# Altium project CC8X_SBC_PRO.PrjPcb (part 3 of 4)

## Sheet 11 - USB HUB.SchDoc: USB HUB
size A3; PageSetup: Record=PageOptions¦CenterHorizontal=True¦CenterVertical=True¦PrintScale=0.70¦XCorrection=1.00¦YCorrection=1.00¦PrintKind=0¦BorderSize=5000000¦LeftOffset=0¦BottomOffset=0¦Orientation=2¦PaperLength=4200¦PaperWidth=2970¦Scale=100¦PaperSource=7¦PrintQuality=600¦MediaType=1¦DitherType=10¦PaperKind=A4¦PrintScaleMode=1; Author: Juan Anzola; SheetNumber: 11; SheetTotal: 17
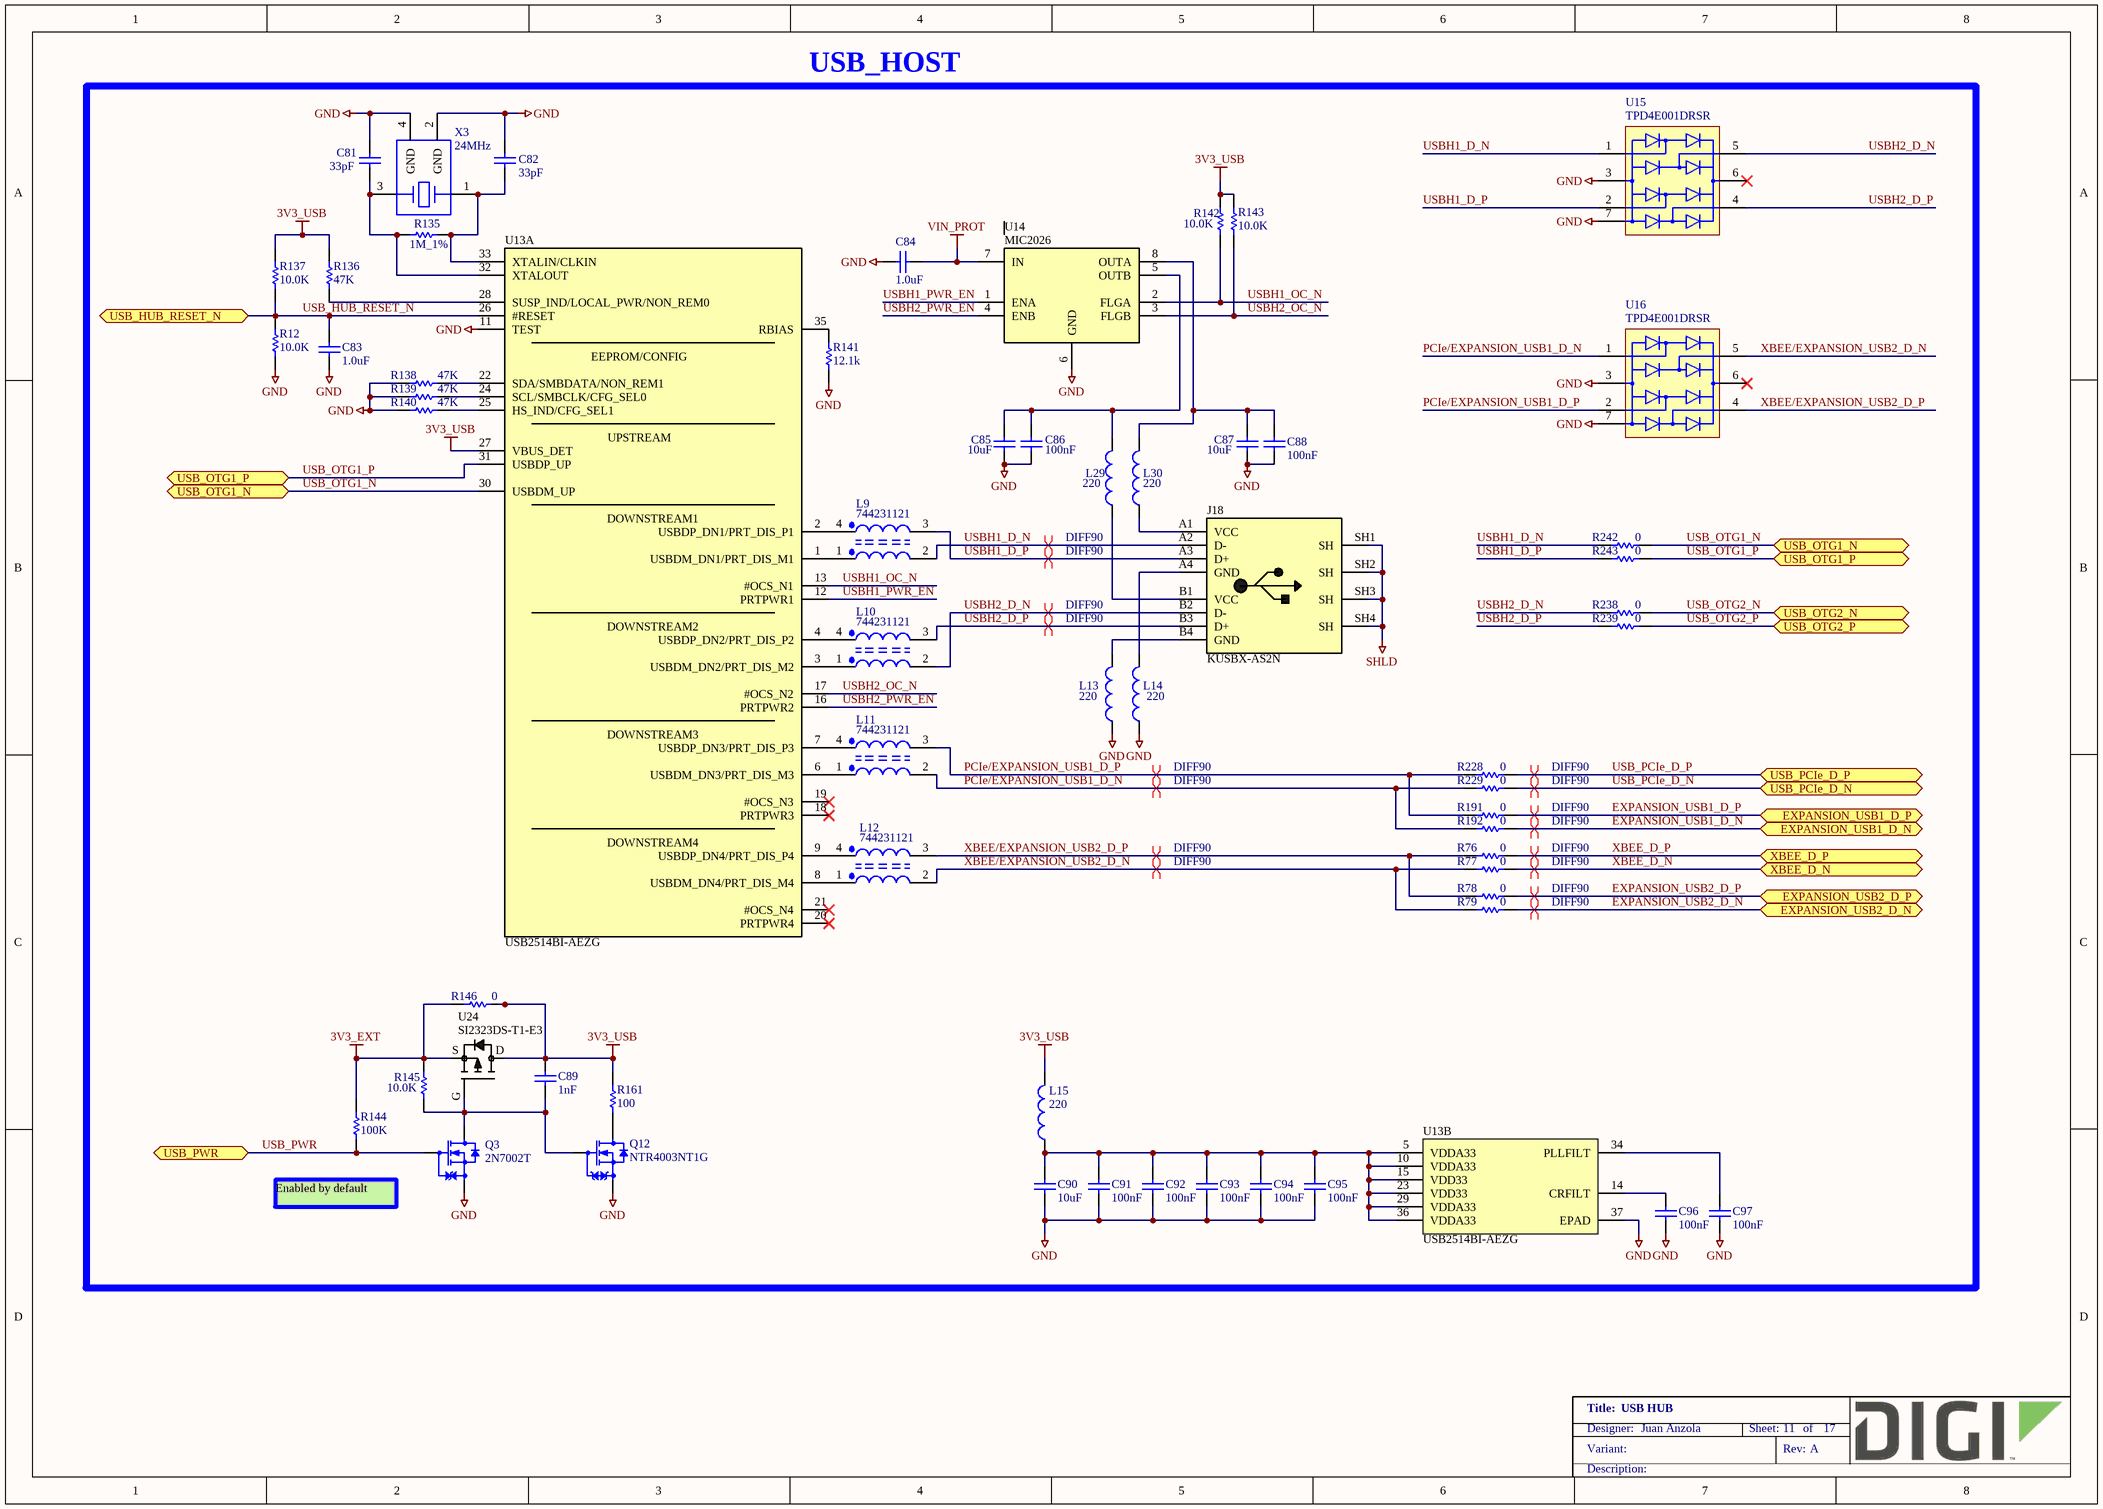
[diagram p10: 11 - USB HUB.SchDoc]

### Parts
C81  33pF  [CAPC1005X55N]
C82  33pF  [CAPC1005X55N]
C83  1.0uF  [CAPC1005X55N]
C84  1.0uF  [CAPC1005X55N]
C85  10uF  [CAPC1005X55N]
C86  100nF  [CAPC1005X55N]
C87  10uF  [CAPC1005X55N]
C88  100nF  [CAPC1005X55N]
C89  1nF  [CAPC1005X55N]
C90  10uF  [CAPC1005X55N]
C91  100nF  [CAPC1005X55N]
C92  100nF  [CAPC1005X55N]
C93  100nF  [CAPC1005X55N]
C94  100nF  [CAPC1005X55N]
C95  100nF  [CAPC1005X55N]
C96  100nF  [CAPC1005X55N]
C97  100nF  [CAPC1005X55N]
J18  KUSBX-AS2N  [KYCON_KUSBX-AS2N_Flex]
L9  744231121  [FIL_DLW21H]
L10  744231121  [FIL_DLW21H]
L11  744231121  [FIL_DLW21H]
L12  744231121  [FIL_DLW21H]
L13  220  [INDC2013X110N]
L14  220  [INDC2013X110N]
L15  220  [INDC2013X110N]
L29  220  [INDC2013X110N]
L30  220  [INDC2013X110N]
Q3  2N7002T  [SOTFL50P160X80_GSD-3N]
Q12  NTR4003NT1G  [SOT95P240X110_GSD-3N]
R12  10.0K  [RESC1005X40N]
R76  0  [RESC1005X40N]
R77  0  [RESC1005X40N]
R78  0  [RESC1005X40N]
R79  0  [RESC1005X40N]
R135  1M_1%  [RESC1005X40N]
R136  47K  [RESC1005X40N]
R137  10.0K  [RESC1005X40N]
R138  47K  [RESC1005X40N]
R139  47K  [RESC1005X40N]
R140  47K  [RESC1005X40N]
R141  12.1k  [RESC1005X40N]
R142  10.0K  [RESC1005X40N]
R143  10.0K  [RESC1005X40N]
R144  100K  [RESC1005X40N]
R145  10.0K  [RESC1005X40N]
R146  0  [RESC1609X55N]
R161  100  [RESC1005X40N]
R191  0  [RESC1005X40N]
R192  0  [RESC1005X40N]
R228  0  [RESC1005X40N]
R229  0  [RESC1005X40N]
R238  0  [RESC1005X40N]
R239  0  [RESC1005X40N]
R242  0  [RESC1005X40N]
R243  0  [RESC1005X40N]
U13  USB2514BI-AEZG  [QFN50P600X600X100-37AN]  (parts A,B of 2)
U14  MIC2026  [SOIC127P600X175-8N]
U15  TPD4E001DRSR  [SON95P300X300X80-7N]
U16  TPD4E001DRSR  [SON95P300X300X80-7N]
U24  SI2323DS-T1-E3  [SOT95P240X110_GSD-3N]
X3  24MHz  [XTAL_C3E-3427]

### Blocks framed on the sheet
USB_HOST: C81-C97 J18 L9-L15 L29 L30 Q3 Q12 R12 R76-R79 R135-R146 R161 R191 R192 R228 R229 R238 R239 R242 R243 U13-U16 U24 X3

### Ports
EXPANSION_USB1_D_N (bidir), EXPANSION_USB1_D_P (bidir), EXPANSION_USB2_D_N (bidir), EXPANSION_USB2_D_P (bidir), USB_HUB_RESET_N (bidir), USB_OTG1_N (bidir), USB_OTG1_P (bidir), USB_OTG2_N (bidir), USB_OTG2_P (bidir), USB_PCIe_D_N (bidir), USB_PCIe_D_P (bidir), USB_PWR (bidir), XBEE_D_N (bidir), XBEE_D_P (bidir)

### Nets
3V3_EXT: R144.1 R145.1 R146.1 U24.S
3V3_USB: C89.2 L15.2 R136.2 R137.2 R142.2 R143.2 R146.2 R161.2 U13.27(VBUS_DET) U24.D
GND: C81.2 C82.2 C83.1 C84.2 C85.1 C86.1 C87.1 C88.1 C90.1 C91.1 C92.1 C93.1 C94.1 C95.1 C96.1 C97.1 L13.1 L14.1 Q3.S Q12.S R12.1 R138.1 R139.1 R140.1 R141.1 U13.11(TEST) U13.37(EPAD) U14.6(GND) U15.3(GND) U15.7(GND) U16.3(GND) U16.7(GND) X3.2(GND) X3.4(GND)
SHLD: J18.SH1(SH) J18.SH2(SH) J18.SH3(SH) J18.SH4(SH)
VIN_PROT: C84.1 U14.7(IN)
EXPANSION_USB1_D_N: R192.2 ; port EXPANSION_USB1_D_N
EXPANSION_USB1_D_P: R191.2 ; port EXPANSION_USB1_D_P
EXPANSION_USB2_D_N: R79.2 ; port EXPANSION_USB2_D_N
EXPANSION_USB2_D_P: R78.2 ; port EXPANSION_USB2_D_P
PCIe/EXPANSION_USB1_D_N: L11.2 R192.1 R229.1 U16.1(I/O)
PCIe/EXPANSION_USB1_D_P: L11.3 R191.1 R228.1 U16.2(I/O)
USB_HUB_RESET_N: C83.2 R12.2 R137.1 U13.26(#RESET) ; port USB_HUB_RESET_N
USB_OTG1_N: R242.2 U13.30(USBDM_UP) ; port USB_OTG1_N
USB_OTG1_P: R243.2 U13.31(USBDP_UP) ; port USB_OTG1_P
USB_OTG2_N: R238.2 ; port USB_OTG2_N
USB_OTG2_P: R239.2 ; port USB_OTG2_P
USB_PCIe_D_N: R229.2 ; port USB_PCIe_D_N
USB_PCIe_D_P: R228.2 ; port USB_PCIe_D_P
USB_PWR: Q3.G R144.2 ; port USB_PWR
USBH1_D_N: J18.A2(D-) L9.2 R242.1 U15.1(I/O)
USBH1_D_P: J18.A3(D+) L9.3 R243.1 U15.2(I/O)
USBH1_OC_N: R142.1 U13.13(#OCS_N1) U14.2(FLGA)
USBH1_PWR_EN: U13.12(PRTPWR1) U14.1(ENA)
USBH2_D_N: J18.B2(D-) L10.2 R238.1 U15.5(I/O)
USBH2_D_P: J18.B3(D+) L10.3 R239.1 U15.4(I/O)
USBH2_OC_N: R143.1 U13.17(#OCS_N2) U14.3(FLGB)
USBH2_PWR_EN: U13.16(PRTPWR2) U14.4(ENB)
XBEE/EXPANSION_USB2_D_N: L12.2 R77.1 R79.1 U16.5(I/O)
XBEE/EXPANSION_USB2_D_P: L12.3 R76.1 R78.1 U16.4(I/O)
XBEE_D_N: R77.2 ; port XBEE_D_N
XBEE_D_P: R76.2 ; port XBEE_D_P
NetC81_1: C81.1 R135.1 U13.32(XTALOUT) X3.3
NetC82_1: C82.1 R135.2 U13.33(XTALIN/CLKIN) X3.1
NetC85_2: C85.2 C86.2 L29.2 U14.5(OUTB)
NetC87_2: C87.2 C88.2 L30.2 U14.8(OUTA)
NetC89_1: C89.1 Q3.D Q12.G R145.2 U24.G
NetC90_2: C90.2 C91.2 C92.2 C93.2 C94.2 C95.2 L15.1 U13.5(VDDA33) U13.10(VDDA33) U13.15(VDD33) U13.23(VDD33) U13.29(VDDA33) U13.36(VDDA33)
NetC96_2: C96.2 U13.14(CRFILT)
NetC97_2: C97.2 U13.34(PLLFILT)
NetJ18_A1: J18.A1(VCC) L30.1
NetJ18_A4: J18.A4(GND) L14.2
NetJ18_B1: J18.B1(VCC) L29.1
NetJ18_B4: J18.B4(GND) L13.2
NetL9_1: L9.1 U13.1(USBDM_DN1/PRT_DIS_M1)
NetL9_4: L9.4 U13.2(USBDP_DN1/PRT_DIS_P1)
NetL10_1: L10.1 U13.3(USBDM_DN2/PRT_DIS_M2)
NetL10_4: L10.4 U13.4(USBDP_DN2/PRT_DIS_P2)
NetL11_1: L11.1 U13.6(USBDM_DN3/PRT_DIS_M3)
NetL11_4: L11.4 U13.7(USBDP_DN3/PRT_DIS_P3)
NetL12_1: L12.1 U13.8(USBDM_DN4/PRT_DIS_M4)
NetL12_4: L12.4 U13.9(USBDP_DN4/PRT_DIS_P4)
NetQ12_D: Q12.D R161.1
NetR136_1: R136.1 U13.28(SUSP_IND/LOCAL_PWR/NON_REM0)
NetR138_2: R138.2 U13.22(SDA/SMBDATA/NON_REM1)
NetR139_2: R139.2 U13.24(SCL/SMBCLK/CFG_SEL0)
NetR140_2: R140.2 U13.25(HS_IND/CFG_SEL1)
NetR141_2: R141.2 U13.35(RBIAS)

Not connected (* = marked no-connect by the designer): U13 18(PRTPWR3)* 19(#OCS_N3)* 20(PRTPWR4)* 21(#OCS_N4)*; U15 6(VCC)*; U16 6(VCC)*

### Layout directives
differential pair; net class DIFF90: EXPANSION_USB1_D_N, EXPANSION_USB1_D_P, EXPANSION_USB2_D_N, EXPANSION_USB2_D_P, PCIe/EXPANSION_USB1_D_N, PCIe/EXPANSION_USB1_D_P, USB_PCIe_D_N, USB_PCIe_D_P, USBH1_D_N, USBH1_D_P, USBH2_D_N, USBH2_D_P, XBEE/EXPANSION_USB2_D_N, XBEE/EXPANSION_USB2_D_P, XBEE_D_N, XBEE_D_P

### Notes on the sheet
- Enabled by default

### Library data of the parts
C81 C82 = 1002646: CAP CER 33PF 50V C0G/NP0 0402; Part_Type: Capacitor; Manufacturer: Murata; Manufacturer_Part_Number: GCM1555C1H330JA16D; Digi_PN: 14050400; Component_Life_Cycle_State: Reviewed; Area: 2,12; Voltage: 50; Tolerance: 5%
C83 C84 = 1001167: CAP CER 1UF 10V 10% X5R 0402; Part_Type: Capacitor; Manufacturer: Murata; Manufacturer_Part_Number: GRM155R61A105KE15D; Digi_PN: 14050399; Component_Life_Cycle_State: Reviewed; Area: 0.95; Project: CCWMX6_SBC board
C85 C87 C90 = 1001168: CAP CER 10UF 10V 20% X5R 0402; Part_Type: Capacitor; Manufacturer: Samsung; Manufacturer_Part_Number: CL05A106MP5NUNC; Digi_PN: 14050689; Component_Life_Cycle_State: Reviewed; Area: 0.95; Project: CCWMX6_SBC board
C86 C88 C91-C97 = 1000006: CAP 100nF 16V 10% X7R 0402; Part_Type: Capacitor; Manufacturer: Murata; Manufacturer_Part_Number: GRM155R71C104KA88D; Component_Life_Cycle_State: CAD Reviewed; Area: 0.95; Project: KITT; Tolerance: 10; Digi_PN: 14050552
C89 = 1000067: CAP CER 1000PF 50V 10% X7R 0402; Part_Type: Capacitor; Manufacturer: Murata; Manufacturer_Part_Number: GRM155R71H102KA01D; Digi_PN: 14050737; Component_Life_Cycle_State: Proven; Area: 0,95; Project: Adjustable Foundation
J18 = 1001121: USB Stacked Dual A type; Part_Type: Connector; Manufacturer: KYCON; Digi_PN: 18000276; Component_Life_Cycle_State: Reviewed; Area: 164; Project: CCWMX6_SBC board
L9-L12 = 1001173: CHOKE COM MODE 120 OHM .37A; Part_Type: Inductor; Manufacturer: Wurth Electronics Inc; Digi_PN: 21000143; Component_Life_Cycle_State: Reviewed; Area: 2.4; Project: CCWMX6_SBC board
L13-L15 L29 L30 = 1001174: FERRITE BEAD 220 OHM 2.0A 0805; Manufacturer: Wurth Electronics Inc; Manufacturer_Part_Number: 742792022; Digi_PN: 21000146; Component_Life_Cycle_State: Reviewed; Area: 4.24; Project: CCWMX6_SBC board
Q3 = 1000715: MOSFET N-CH 60V 115MA SOT-523F; Part_Type: Transistor; Manufacturer: Fairchild Semiconductor; Digi_PN: 17050797; Component_Life_Cycle_State: CAD Reviewed; Area: 3.06; Project: SmartMeter2; Note: 17050841 = Digi No. for GE WDNU
Q12 = 1000306: MOSFET N-CH 30V 500MA SOT-23; Part_Type: Transistor; Manufacturer: On Semiconductor; Digi_PN: 17050809; Component_Life_Cycle_State: Proven; Area: 10,92; Project: Adjustable Foundation
R12 R137 R142 R143 R145 = 1000537: RES 10.0K OHM 1/10W 1% 0402 SMD; Part_Type: Resistor; Manufacturer: Panasonic - ECG; Manufacturer_Part_Number: ERJ-2RKF1002X; Component_Life_Cycle_State: CAD Reviewed; Area: 0.95; Project: KITT; Power_WV_SRF: 100; Digi_PN: 13051084
R76-R79 R191 R192 R228 R229 R238 R239 R242 R243 = 1000076: RES 0.0 OHM 1/10W 0402 SMD; Part_Type: Resistor; Manufacturer: Panasonic - ECG; Manufacturer_Part_Number: ERJ-2GE0R00X; Component_Life_Cycle_State: Proven; Area: 0.95; Project: Adjustable Foundation; Power_WV_SRF: 10; Digi_PN: 13050387
R135 = 1000971: RES 1.00M OHM 1/16W 1% 0402 SMD; Part_Type: Resistor; Manufacturer: Yageo; Manufacturer_Part_Number: RC0402FR-071ML; Digi_PN: 13050561; Component_Life_Cycle_State: Reviewed; Area: 0.95; Project: ConnectCore i.MX6 module; Power_WV_SRF: 63; Tolerance: 1; Note: 13051098 = Digi No. for GE WDNU
R136 R138-R140 = 1001155: RES 47.0K OHM 1/16W 1% 0402 SMD; Part_Type: Resistor; Manufacturer: Vishay Dale; Manufacturer_Part_Number: CRCW040247K0FKED; Digi_PN: 13050646; Component_Life_Cycle_State: Reviewed; Area: 0.95; Project: CCWMX6_SBC board
R141 = 1000828: RES 12.1K OHM 1/10W 1% 0402 SMD; Part_Type: Resistor; Manufacturer: Panasonic - ECG; Manufacturer_Part_Number: ERJ-2RKF1212X; Component_Life_Cycle_State: Reviewed; Area: 0.95; Project: SmartMeter2; Power_WV_SRF: 100; Digi_PN: 13051088
R144 = 1000480: RES 100K OHM 1/10W 1% 0402 SMD; Part_Type: Resistor; Manufacturer: Panasonic - ECG; Manufacturer_Part_Number: ERJ-2RKF1003X; Digi_PN: 13051063; Component_Life_Cycle_State: CAD Reviewed; Area: 0.95; Project: KITT; Power_WV_SRF: 100
R146 = 1000208: RES 0.0 OHM 1/10W 0603; Part_Type: Resistor; Manufacturer: Panasonic - ECG; Manufacturer_Part_Number: ERJ-3GEY0R00V; Note: 13051103 = Digi No. for GE WDNU; Digi_PN: 13050568; Component_Life_Cycle_State: Reviewed; Area: 2.5; Project: Adjustable Foundation; Voltage: 75V
R161 = 1000467: RES 100 OHM 1/10W 1% 0402 SMD; Part_Type: Resistor; Manufacturer: Panasonic - ECG; Manufacturer_Part_Number: ERJ-2RKF1000X; Digi_PN: 13051087; Component_Life_Cycle_State: CAD Reviewed; Area: 0,95; Project: KITT
U13 = 1001114: 4-PORT USB 2.0 HUB CTRLR 36VQFN; Part_Type: IC; Manufacturer: SMSC; Digi_PN: 16051280; Component_Life_Cycle_State: Reviewed; Area: 36; Project: CCWMX6_SBC board
U14 = 1001143: IC SW DISTRIBUTION 2CHAN 8SOIC; Manufacturer: Micrel; Manufacturer_Part_Number: MIC2026-1YM; Digi_PN: 16051879; Component_Life_Cycle_State: Reviewed; Area: 29.58; Project: CCWMX6_SBC board
U15 U16 = 1001265: TVS DIODE 5.5VWM 6SON; Part_Type: IC; Manufacturer: Texas Instruments; Digi_PN: 17050690; Component_Life_Cycle_State: Reviewed; Area: 10; Project: CCWMX6_SBC board; Note: 17050839 = Digi No. for GE WDNU
U24 = 1001163: MOSFET P-CH 20V 3.7A SOT23-3; Part_Type: IC; Manufacturer: Vishay Siliconix; Digi_PN: 17050358; Component_Life_Cycle_State: Reviewed; Area: 10.92; Project: CCWMX6_SBC board
X3 = 1001134: CRYSTAL 24MHZ 18PF SMD; Part_Type: Crystals-Oscillators; Manufacturer: Aker; Manufacturer_Part_Number: C3E-24.000-18-3030-X-R; Digi_PN: 20000223; Component_Life_Cycle_State: Reviewed; Area: 9.18; Project: CCWMX6_SBC board

## Sheet 12 - USB Type C, USB microAB.SchDoc: USB Type C, USB mciroAB
size A3; PageSetup: Record=PageOptions¦CenterHorizontal=True¦CenterVertical=True¦PrintScale=0.70¦XCorrection=1.00¦YCorrection=1.00¦PrintKind=0¦BorderSize=5000000¦LeftOffset=0¦BottomOffset=0¦Orientation=2¦PaperLength=4200¦PaperWidth=2970¦Scale=100¦PaperSource=7¦PrintQuality=600¦MediaType=1¦DitherType=10¦PaperKind=A4¦PrintScaleMode=1; Author: Juan Anzola; SheetNumber: 12; SheetTotal: 17
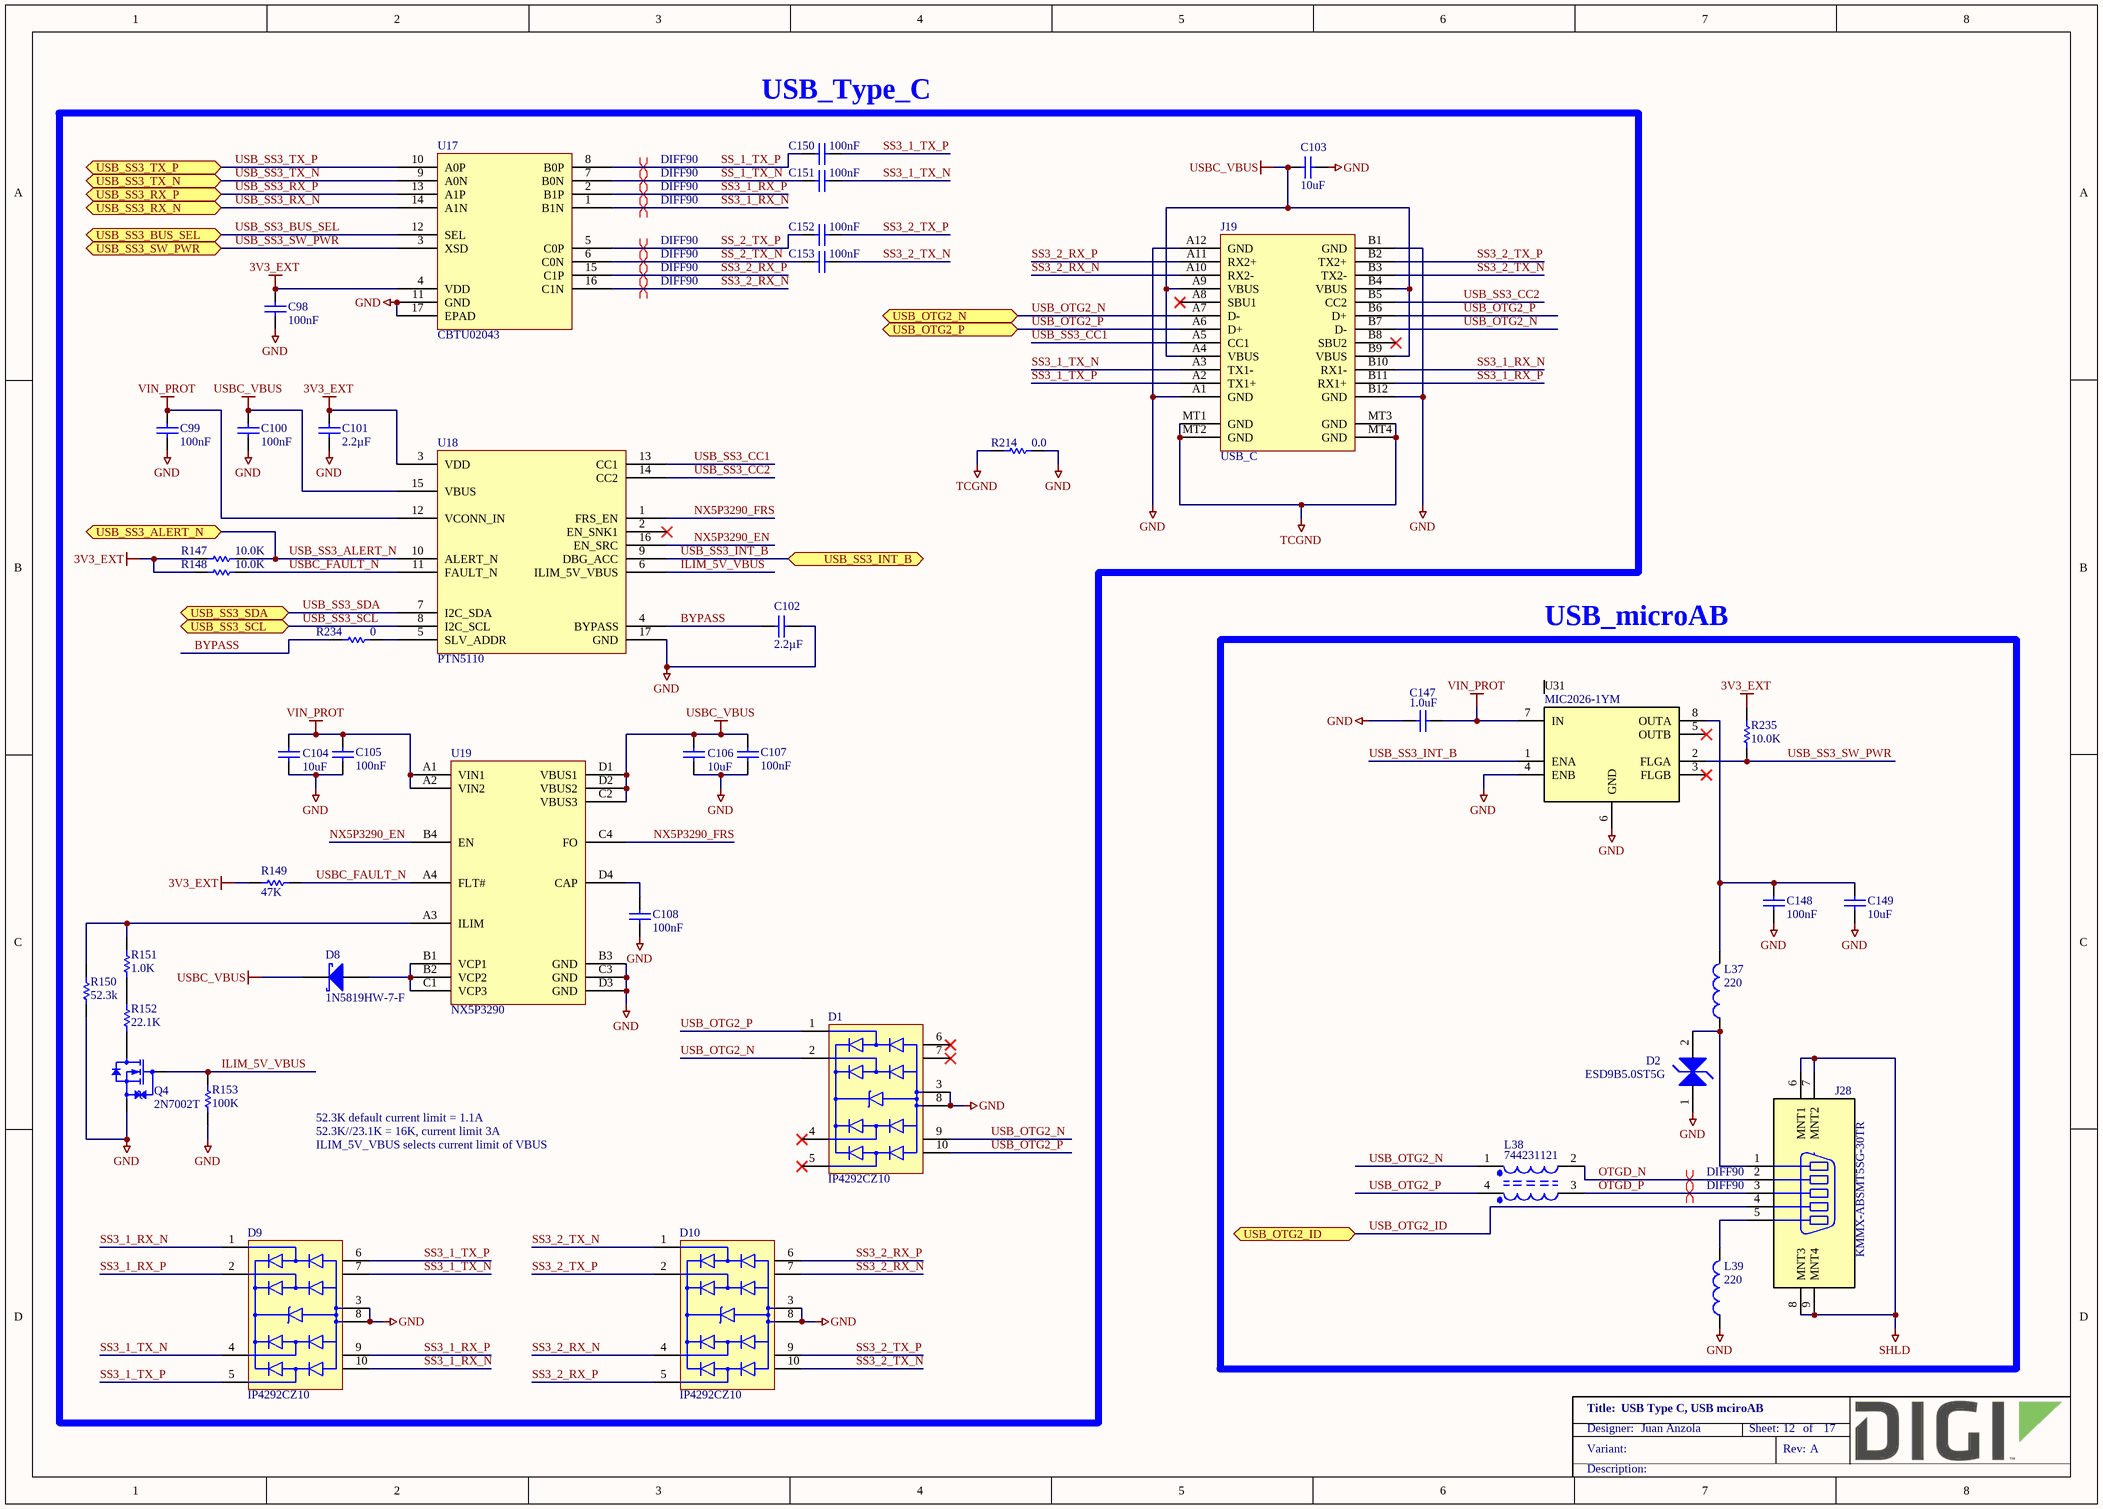
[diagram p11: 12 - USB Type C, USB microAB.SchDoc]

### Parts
C98  100nF  [CAPC1005X55N]
C99  100nF  [CAPC1005X55N]
C100  100nF  [CAPC1005X55N]
C101  2.2µF  [CAPC1005X55L]
C102  2.2µF  [CAPC1005X55L]
C103  10uF  [CAPC1005X55N]
C104  10uF  [CAPC1005X55N]
C105  100nF  [CAPC1005X55N]
C106  10uF  [CAPC1005X55N]
C107  100nF  [CAPC1005X55N]
C108  100nF  [CAPC1005X55N]
C147  1.0uF  [CAPC1005X55N]
C148  100nF  [CAPC1005X55N]
C149  10uF  [CAPC1005X55N]
C150  100nF  [CAPC1005X55N]
C151  100nF  [CAPC1005X55N]
C152  100nF  [CAPC1005X55N]
C153  100nF  [CAPC1005X55N]
D1  IP4292CZ10  [SON50P250X100X50-10N]
D2  ESD9B5.0ST5G  [SODFL1006X43N12]
D8  1N5819HW-7-F  [SOD3716X135N]
D9  IP4292CZ10  [SON50P250X100X50-10N]
D10  IP4292CZ10  [SON50P250X100X50-10N]
J19  USB_C  [MOLEX_201267-0005]
J28  KMMX-ABSMT5SG-30TR  [KYCON_KMMX-ABSMT5]
L37  220  [INDC2013X110N]
L38  744231121  [FIL_DLW21H]
L39  220  [INDC2013X110N]
Q4  2N7002T  [SOTFL50P160X80_GSD-3N]
R147  10.0K  [RESC1005X40N]
R148  10.0K  [RESC1005X40N]
R149  47K  [RESC1005X40N]
R150  52.3k  [RESC1005X40N]
R151  1.0K  [RESC1005X40N]
R152  22.1K  [RESC1005X40N]
R153  100K  [RESC1005X40N]
R214  0.0  [RESC2013X70N]
R234  0  [RESC1005X40N]
R235  10.0K  [RESC1005X40N]
U17  CBTU02043  [PQFN40P160X240X55-17T140X60N]
U18  PTN5110  [QFN40P260X260X40-17T100X110N]
U19  NX5P3290  [BGA16N50P4X4_205X205X59B32N]
U31  Manufacturer_Part_Number: MIC2026-1YM  [SOIC127P600X175-8N]  (hidden comment: MIC2026)

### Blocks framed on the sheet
USB_Type_C: C98-C108 C150-C153 D1 D8-D10 J19 Q4 R147-R153 R214 R234 U17-U19
USB_microAB: C147-C149 D2 J28 L37-L39 R235 U31

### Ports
USB_OTG2_ID (bidir), USB_OTG2_N (bidir), USB_OTG2_P (bidir), USB_SS3_ALERT_N (bidir), USB_SS3_BUS_SEL (bidir), USB_SS3_INT_B (bidir), USB_SS3_RX_N (bidir), USB_SS3_RX_P (bidir), USB_SS3_SCL (bidir), USB_SS3_SDA (bidir), USB_SS3_SW_PWR (bidir), USB_SS3_TX_N (bidir), USB_SS3_TX_P (bidir)

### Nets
3V3_EXT: C98.2 C101.2 R147.1 R148.1 R149.1 R235.2 U17.4(VDD) U18.3(VDD)
GND: C98.1 C99.1 C100.1 C101.1 C102.1 C103.1 C104.1 C105.1 C106.1 C107.1 C108.1 C147.1 C148.1 C149.1 D1.3(GND) D1.8(GND) D2.1 D9.3(GND) D9.8(GND) D10.3(GND) D10.8(GND) J19.A1(GND) J19.A12(GND) J19.B1(GND) J19.B12(GND) L39.1 Q4.S R150.1 R153.1 R214.2 U17.11(GND) U17.17(EPAD) U18.17(GND) U19.B3(GND) U19.C3(GND) U19.D3(GND) U31.4(ENB) U31.6(GND)
SHLD: J28.6(MNT1) J28.7(MNT2) J28.8(MNT3) J28.9(MNT4)
TCGND: J19.MT1(GND) J19.MT2(GND) J19.MT3(GND) J19.MT4(GND) R214.1
USBC_VBUS: C100.2 C103.2 C106.2 C107.2 D8.K J19.A4(VBUS) J19.A9(VBUS) J19.B4(VBUS) J19.B9(VBUS) U18.15(VBUS) U19.C2(VBUS3) U19.D1(VBUS1) U19.D2(VBUS2)
VIN_PROT: C99.2 C104.2 C105.2 C147.2 U18.12(VCONN_IN) U19.A1(VIN1) U19.A2(VIN2) U31.7(IN)
BYPASS: C102.2 R234.2 U18.4(BYPASS)
ILIM_5V_VBUS: Q4.G R153.2 U18.6(ILIM_5V_VBUS)
NX5P3290_EN: U18.16(EN_SRC) U19.B4(EN)
NX5P3290_FRS: U18.1(FRS_EN) U19.C4(FO)
OTGD_N: J28.2 L38.2
OTGD_P: J28.3 L38.3
SS3_1_RX_N: D9.1(CH1) D9.10(NC) J19.B10(RX1-) U17.1(B1N)
SS3_1_RX_P: D9.2(CH2) D9.9(NC) J19.B11(RX1+) U17.2(B1P)
SS3_1_TX_N: C151.2 D9.4(CH3) D9.7(NC) J19.A3(TX1-)
SS3_1_TX_P: C150.2 D9.5(CH4) D9.6(NC) J19.A2(TX1+)
SS3_2_RX_N: D10.4(CH3) D10.7(NC) J19.A10(RX2-) U17.16(C1N)
SS3_2_RX_P: D10.5(CH4) D10.6(NC) J19.A11(RX2+) U17.15(C1P)
SS3_2_TX_N: C153.2 D10.1(CH1) D10.10(NC) J19.B3(TX2-)
SS3_2_TX_P: C152.2 D10.2(CH2) D10.9(NC) J19.B2(TX2+)
SS_1_TX_N: C151.1 U17.7(B0N)
SS_1_TX_P: C150.1 U17.8(B0P)
SS_2_TX_N: C153.1 U17.6(C0N)
SS_2_TX_P: C152.1 U17.5(C0P)
USB_OTG2_ID: J28.4 ; port USB_OTG2_ID
USB_OTG2_N: D1.2(CH2) D1.9(NC) J19.A7(D-) J19.B7(D-) L38.1 ; port USB_OTG2_N
USB_OTG2_P: D1.1(CH1) D1.10(NC) J19.A6(D+) J19.B6(D+) L38.4 ; port USB_OTG2_P
USB_SS3_ALERT_N: R147.2 U18.10(ALERT_N) ; port USB_SS3_ALERT_N
USB_SS3_BUS_SEL: U17.12(SEL) ; port USB_SS3_BUS_SEL
USB_SS3_CC1: J19.A5(CC1) U18.13(CC1)
USB_SS3_CC2: J19.B5(CC2) U18.14(CC2)
USB_SS3_INT_B: U18.9(DBG_ACC) U31.1(ENA) ; port USB_SS3_INT_B
USB_SS3_RX_N: U17.14(A1N) ; port USB_SS3_RX_N
USB_SS3_RX_P: U17.13(A1P) ; port USB_SS3_RX_P
USB_SS3_SCL: U18.8(I2C_SCL) ; port USB_SS3_SCL
USB_SS3_SDA: U18.7(I2C_SDA) ; port USB_SS3_SDA
USB_SS3_SW_PWR: R235.1 U17.3(XSD) U31.2(FLGA) ; port USB_SS3_SW_PWR
USB_SS3_TX_N: U17.9(A0N) ; port USB_SS3_TX_N
USB_SS3_TX_P: U17.10(A0P) ; port USB_SS3_TX_P
USBC_FAULT_N: R148.2 R149.2 U18.11(FAULT_N) U19.A4(FLT#)
NetC108_2: C108.2 U19.D4(CAP)
NetC148_2: C148.2 C149.2 L37.2 U31.8(OUTA)
NetD2_2: D2.2 J28.1 L37.1
NetD8_A: D8.A U19.B1(VCP1) U19.B2(VCP2) U19.C1(VCP3)
NetJ28_5: J28.5 L39.2
NetQ4_D: Q4.D R152.1
NetR150_2: R150.2 R151.2 U19.A3(ILIM)
NetR151_1: R151.1 R152.2
NetR234_1: R234.1 U18.5(SLV_ADDR)

Not connected (* = marked no-connect by the designer): D1 4(CH3)* 5(CH4)* 6(NC)* 7(NC)*; J19 A8(SBU1)* B8(SBU2)*; U18 2(EN_SNK1)*; U31 3(FLGB)* 5(OUTB)*

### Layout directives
differential pair; net class DIFF90: OTGD_N, OTGD_P, SS3_1_RX_N, SS3_1_RX_P, SS3_2_RX_N, SS3_2_RX_P, SS_1_TX_N, SS_1_TX_P, SS_2_TX_N, SS_2_TX_P

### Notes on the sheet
- 52.3K default current limit = 1.1A
- 52.3K//23.1K = 16K, current limit 3A
- ILIM_5V_VBUS selects current limit of VBUS

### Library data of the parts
C98-C100 C105 C107 C108 C148 = 1000006: as C86 on sheet 11 - USB HUB
C101 C102 = 1000970: CAP CER 2.2UF 6.3V 20% X5R 0402; Part_Type: Capacitor; Manufacturer: TDK Corporation; Manufacturer_Part_Number: C1005X5R0J225M050BC; Manufacturer_Alt_1: Taiyo Yuden; Manufacturer_Alt_1_Part_Number: JMK105BJ225MV-F; Note: 14050756 = Digi No. for GE WDNU; Digi_PN: 14050493; Component_Life_Cycle_State: Reviewed; Area: 0.5; Project: ConnectCore i.MX6 module; Tolerance: 20
C103 C104 C106 C149 = 1001168: as C85 on sheet 11 - USB HUB
C147 = 1001167: as C83 on sheet 11 - USB HUB
C150-C153 = 1000918: CAP CER 0.1UF 50V 10% X7R 0402; Part_Type: Capacitor; Manufacturer: TDK Corporation; Manufacturer_Part_Number: C1005X7R1H104K050BB; Digi_PN: 14050715; Component_Life_Cycle_State: Reviewed; Area: 0,95; Project: DTM3.0
D1 D9 D10 = 1002593: TVS DIODE 5.5V 4V 10DFN; Part_Type: Circuit Protection; Manufacturer: Phillips NXP; Digi_PN: 17000143; Component_Life_Cycle_State: Created; Area: 7,24; Project: DIGI CC8X SOM
D2 = 1001264: TVS DIODE 5VWM SOD923; Part_Type: Diodes; Manufacturer: On Semiconductor; Digi_PN: 17050587; Component_Life_Cycle_State: Reviewed; Area: 1.5; Project: CCWMX6_SBC board
D8 = 1000231: DIODE SCHOTTKY 40V 1A SOD123; Part_Type: Diodes; Manufacturer: Diodes, Inc.; Digi_PN: 17000146; Component_Life_Cycle_State: Proven; Area: 8.28; Project: Adjustable Foundation
J19 = 1002675: USB 3.1 SHIELDED I/O RECP TYPE C GEN2; Part_Type: Connector; Manufacturer: Molex; Manufacturer_Part_Number: 201267-0005; Digi_PN: 18000775; Component_Life_Cycle_State: Created; Area: 86.57; Project: DIGI CC8X SOM
J28 = 1001117: CONN RECEPT MICRO-USB TYPE AB R/A; Part_Type: Connector; Manufacturer: KYCON; Digi_PN: 18000401; Component_Life_Cycle_State: Reviewed; Area: 40; Project: CCWMX6_SBC board
L37 L39 = 1001174: as L13-L15 on sheet 11 - USB HUB
L38 = 1001173: as L9 on sheet 11 - USB HUB
Q4 = 1000715: as Q3 on sheet 11 - USB HUB
R147 R148 R235 = 1000537: as R12 on sheet 11 - USB HUB
R149 = 1001155: RES 47.0K OHM 1/16W 1% 0402 SMD; Part_Type: Resistor; Manufacturer: Vishay Dale; Manufacturer_Part_Number: CRCW040247K0FKED; Digi_PN: 13050646; Component_Life_Cycle_State: Reviewed; Area: 0,95; Project: CCWMX6_SBC board
R150 = 1000170: RES 52.3K OHM 1/10W 1% 0402 SMD; Part_Type: Resistor; Manufacturer: Panasonic - ECG; Manufacturer_Part_Number: ERJ-2RKF5232X; Digi_PN: 13000085; Component_Life_Cycle_State: Reviewed; Area: 0.95; Project: USB UART to USB Transceiver; Power_WV_SRF: 10
R151 = 1000079: RES 1.00K OHM 1/10W 1% 0402 SMD; Part_Type: Resistor; Manufacturer: Panasonic - ECG; Manufacturer_Part_Number: ERJ-2RKF1001X; Digi_PN: 13051085; Component_Life_Cycle_State: Proven; Area: 0,95; Project: Adjustable Foundation; Power_WV_SRF: 10
R152 = 1001149: RES 22.1K OHM 1/16W 1% 0402 SMD; Part_Type: Resistor; Manufacturer: Vishay Dale; Manufacturer_Part_Number: CRCW040222K1FKED; Digi_PN: 13050450; Component_Life_Cycle_State: Reviewed; Area: 0,95; Project: CCWMX6_SBC board; Power_WV_SRF: 0,063; Tolerance: ±100ppm/°C
R153 = 1000480: as R144 on sheet 11 - USB HUB
R214 = 1001557: RES 0.0 OHM 1/8W JUMP 0805 SMD; Part_Type: Resistor; Manufacturer: Yageo; Manufacturer_Part_Number: RC0805JR-070RL; Note: 13051095 = Digi No. for GE WDNU; Digi_PN: TR00037; Component_Life_Cycle_State: Reviewed; Area: 5,8; Project: WDNU-II; Power_WV_SRF: 125
R234 = 1000076: RES 0.0 OHM 1/10W 0402 SMD; Part_Type: Resistor; Manufacturer: Panasonic - ECG; Manufacturer_Part_Number: ERJ-2GE0R00X; Digi_PN: 13050387; Component_Life_Cycle_State: Proven; Area: 0,95; Project: Adjustable Foundation; Power_WV_SRF: 10
U17 = 1002584: IC DIFF SWITCH 2:1 HUQFN16; Manufacturer: NXP Semiconductors; Digi_PN: 16000124; Component_Life_Cycle_State: Reviewed; Area: 6.09; Project: DIGI CC8X SOM
U18 = 1002585: IC USB PD TCPC PHY HX2QFN16; Manufacturer: NXP Semiconductors; Digi_PN: 16000125; Component_Life_Cycle_State: Reviewed; Area: 14.75; Project: DIGI CC8X SOM
U19 = 1002586: IC USB POWER SWITCH 16WLCSP; Manufacturer: NXP Semiconductors; Digi_PN: 16000126; Component_Life_Cycle_State: Reviewed; Area: 6.76; Project: DIGI CC8X SOM
U31 = 1001143: IC SW DISTRIBUTION 2CHAN 8SOIC; Manufacturer: Micrel; Digi_PN: 16051879; Component_Life_Cycle_State: Reviewed; Area: 29.58; Project: CCWMX6_SBC board

## Sheet 13 - Audio.SchDoc: Audio
size A3; PageSetup: Record=PageOptions¦CenterHorizontal=True¦CenterVertical=True¦PrintScale=0.70¦XCorrection=1.00¦YCorrection=1.00¦PrintKind=0¦BorderSize=5000000¦LeftOffset=0¦BottomOffset=0¦Orientation=2¦PaperLength=4200¦PaperWidth=2970¦Scale=100¦PaperSource=7¦PrintQuality=600¦MediaType=1¦DitherType=10¦PaperKind=A4¦PrintScaleMode=1; Author: Juan Anzola; SheetNumber: 13; SheetTotal: 17
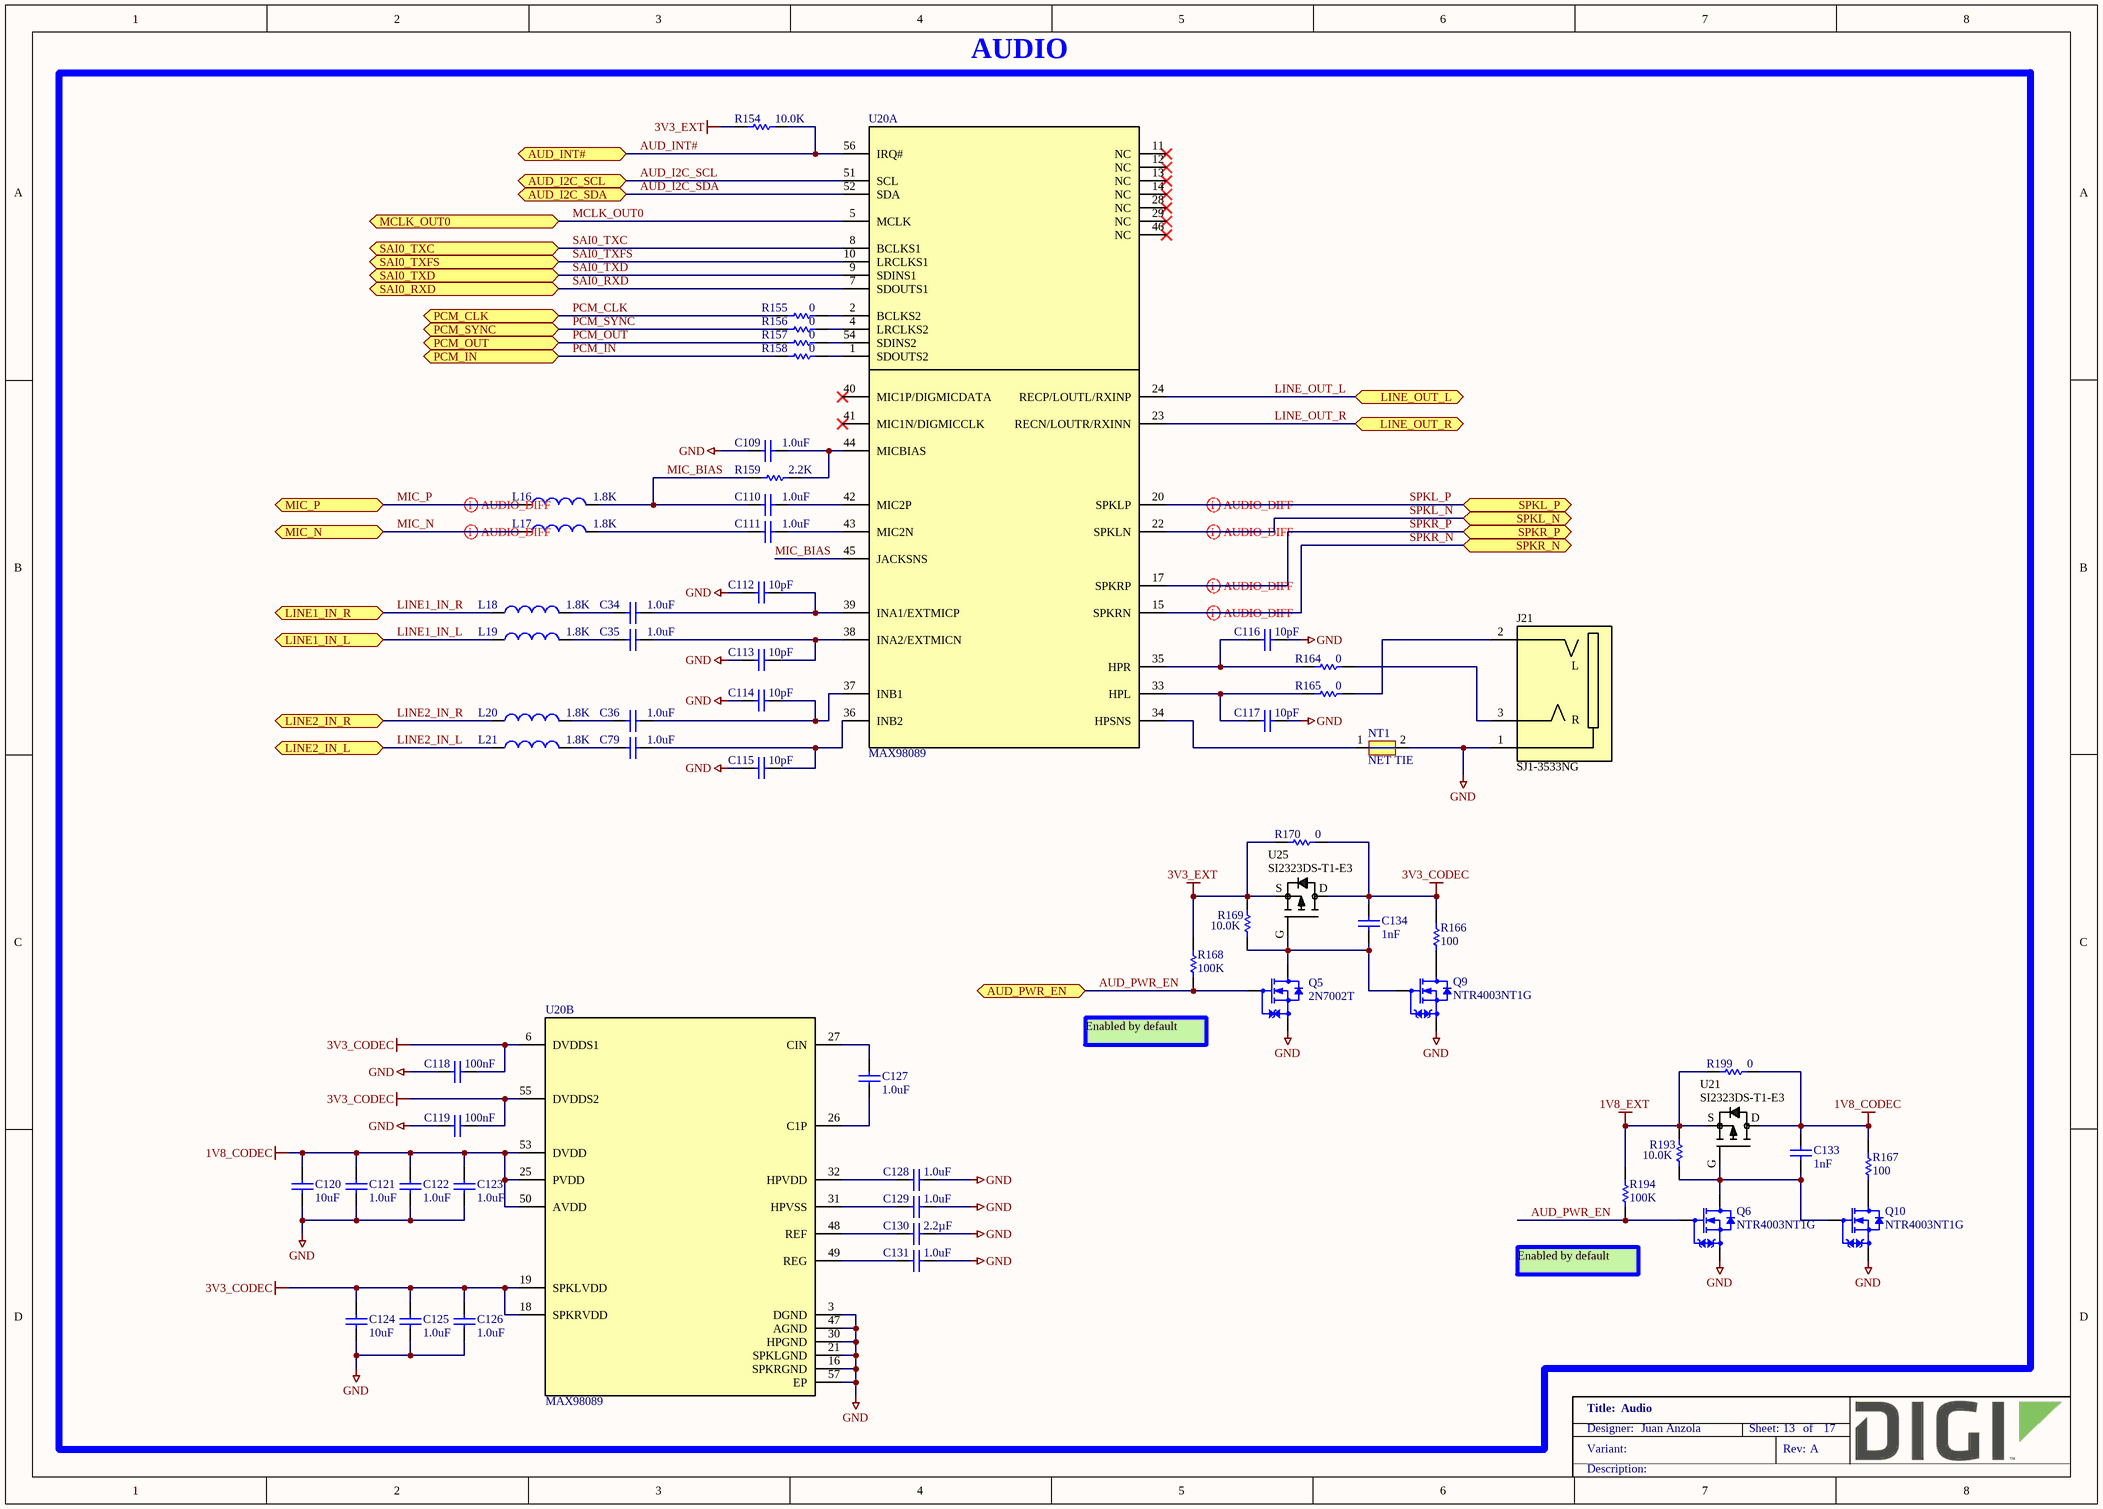
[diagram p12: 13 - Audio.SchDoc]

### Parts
C34  1.0uF  [CAPC1005X55L]
C35  1.0uF  [CAPC1005X55L]
C36  1.0uF  [CAPC1005X55L]
C79  1.0uF  [CAPC1005X55L]
C109  1.0uF  [CAPC1005X55L]
C110  1.0uF  [CAPC1005X55L]
C111  1.0uF  [CAPC1005X55L]
C112  10pF  [CAPC1005X55N]
C113  10pF  [CAPC1005X55N]
C114  10pF  [CAPC1005X55N]
C115  10pF  [CAPC1005X55N]
C116  10pF  [CAPC1005X55N]
C117  10pF  [CAPC1005X55N]
C118  100nF  [CAPC1005X55N]
C119  100nF  [CAPC1005X55N]
C120  10uF  [CAPC1005X55N]
C121  1.0uF  [CAPC1005X55N]
C122  1.0uF  [CAPC1005X55N]
C123  1.0uF  [CAPC1005X55N]
C124  10uF  [CAPC1005X55N]
C125  1.0uF  [CAPC1005X55N]
C126  1.0uF  [CAPC1005X55N]
C127  1.0uF  [CAPC1005X55N]
C128  1.0uF  [CAPC1005X55N]
C129  1.0uF  [CAPC1005X55N]
C130  2.2µF  [CAPC1005X55N]
C131  1.0uF  [CAPC1005X55N]
C133  1nF  [CAPC1005X55N]
C134  1nF  [CAPC1005X55N]
J21  SJ1-3533NG  [CUI_SJ1-3533N]
L16  1.8K  [INDC1005X60N]
L17  1.8K  [INDC1005X60N]
L18  1.8K  [INDC1005X60N]
L19  1.8K  [INDC1005X60N]
L20  1.8K  [INDC1005X60N]
L21  1.8K  [INDC1005X60N]
NT1  NET TIE  [NET_TIE_4mil]  (net tie, no BOM)
Q5  2N7002T  [SOTFL50P160X80_GSD-3N]
Q6  NTR4003NT1G  [SOT95P240X110_GSD-3N]
Q9  NTR4003NT1G  [SOT95P240X110_GSD-3N]
Q10  NTR4003NT1G  [SOT95P240X110_GSD-3N]
R154  10.0K  [RESC1005X40N]
R155  0  [RESC1005X40N]
R156  0  [RESC1005X40N]
R157  0  [RESC1005X40N]
R158  0  [RESC1005X40N]
R159  2.2K  [RESC1005X40N]
R164  0  [RESC1005X40N]
R165  0  [RESC1005X40N]
R166  100  [RESC1005X40N]
R167  100  [RESC1005X40N]
R168  100K  [RESC1005X40N]
R169  10.0K  [RESC1005X40N]
R170  0  [RESC1609X55N]
R193  10.0K  [RESC1005X40N]
R194  100K  [RESC1005X40N]
R199  0  [RESC1609X55N]
U20  MAX98089  [QFN40P700X700X80-57T560X560N]  (parts A,B of 2)
U21  SI2323DS-T1-E3  [SOT95P240X110_GSD-3N]
U25  SI2323DS-T1-E3  [SOT95P240X110_GSD-3N]

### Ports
AUD_I2C_SCL (bidir), AUD_I2C_SDA (bidir), AUD_INT# (bidir), AUD_PWR_EN (bidir), LINE1_IN_L (bidir), LINE1_IN_R (bidir), LINE2_IN_L (bidir), LINE2_IN_R (bidir), LINE_OUT_L (bidir), LINE_OUT_R (bidir), MCLK_OUT0 (bidir), MIC_N (bidir), MIC_P (bidir), PCM_CLK (bidir), PCM_IN (bidir), PCM_OUT (bidir), PCM_SYNC (bidir), SAI0_RXD (bidir), SAI0_TXC (bidir), SAI0_TXD (bidir), SAI0_TXFS (bidir), SPKL_N (bidir), SPKL_P (bidir), SPKR_N (bidir), SPKR_P (bidir)

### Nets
1V8_CODEC: C120.2 C121.1 C122.1 C123.1 C133.2 R167.2 R199.2 U20.25(PVDD) U20.50(AVDD) U20.53(DVDD) U21.D
1V8_EXT: R193.1 R194.1 R199.1 U21.S
3V3_CODEC: C118.1 C119.1 C124.2 C125.1 C126.1 C134.2 R166.2 R170.2 U20.6(DVDDS1) U20.18(SPKRVDD) U20.19(SPKLVDD) U20.55(DVDDS2) U25.D
3V3_EXT: R154.1 R168.1 R169.1 R170.1 U25.S
GND: C109.2 C112.2 C113.2 C114.2 C115.2 C116.2 C117.2 C118.2 C119.2 C120.1 C121.2 C122.2 C123.2 C124.1 C125.2 C126.2 C128.1 C129.1 C130.2 C131.1 J21.1 NT1.2 Q5.S Q6.S Q9.S Q10.S U20.3(DGND) U20.16(SPKRGND) U20.21(SPKLGND) U20.30(HPGND) U20.47(AGND) U20.57(EP)
AUD_I2C_SCL: U20.51(SCL) ; port AUD_I2C_SCL
AUD_I2C_SDA: U20.52(SDA) ; port AUD_I2C_SDA
AUD_INT#: R154.2 U20.56(IRQ#) ; port AUD_INT#
AUD_PWR_EN: Q5.G Q6.G R168.2 R194.2 ; port AUD_PWR_EN
LINE1_IN_L: L19.1 ; port LINE1_IN_L
LINE1_IN_R: L18.1 ; port LINE1_IN_R
LINE2_IN_L: L21.1 ; port LINE2_IN_L
LINE2_IN_R: L20.1 ; port LINE2_IN_R
LINE_OUT_L: U20.24(RECP/LOUTL/RXINP) ; port LINE_OUT_L
LINE_OUT_R: U20.23(RECN/LOUTR/RXINN) ; port LINE_OUT_R
MCLK_OUT0: U20.5(MCLK) ; port MCLK_OUT0
MIC_BIAS: C110.2 L16.2 R159.1 U20.45(JACKSNS)
MIC_N: L17.1 ; port MIC_N
MIC_P: L16.1 ; port MIC_P
PCM_CLK: R155.1 ; port PCM_CLK
PCM_IN: R158.1 ; port PCM_IN
PCM_OUT: R157.1 ; port PCM_OUT
PCM_SYNC: R156.1 ; port PCM_SYNC
SAI0_RXD: U20.7(SDOUTS1) ; port SAI0_RXD
SAI0_TXC: U20.8(BCLKS1) ; port SAI0_TXC
SAI0_TXD: U20.9(SDINS1) ; port SAI0_TXD
SAI0_TXFS: U20.10(LRCLKS1) ; port SAI0_TXFS
SPKL_N: U20.22(SPKLN) ; port SPKL_N
SPKL_P: U20.20(SPKLP) ; port SPKL_P
SPKR_N: U20.15(SPKRN) ; port SPKR_N
SPKR_P: U20.17(SPKRP) ; port SPKR_P
NetC34_1: C34.1 C112.1 U20.39(INA1/EXTMICP)
NetC34_2: C34.2 L18.2
NetC35_1: C35.1 C113.1 U20.38(INA2/EXTMICN)
NetC35_2: C35.2 L19.2
NetC36_1: C36.1 C114.1 U20.37(INB1)
NetC36_2: C36.2 L20.2
NetC79_1: C79.1 C115.1 U20.36(INB2)
NetC79_2: C79.2 L21.2
NetC109_1: C109.1 R159.2 U20.44(MICBIAS)
NetC110_1: C110.1 U20.42(MIC2P)
NetC111_1: C111.1 U20.43(MIC2N)
NetC111_2: C111.2 L17.2
NetC116_1: C116.1 R164.1 U20.35(HPR)
NetC117_1: C117.1 R165.1 U20.33(HPL)
NetC127_1: C127.1 U20.27(CIN)
NetC127_2: C127.2 U20.26(C1P)
NetC128_2: C128.2 U20.32(HPVDD)
NetC129_2: C129.2 U20.31(HPVSS)
NetC130_1: C130.1 U20.48(REF)
NetC131_2: C131.2 U20.49(REG)
NetC133_1: C133.1 Q6.D Q10.G R193.2 U21.G
NetC134_1: C134.1 Q5.D Q9.G R169.2 U25.G
NetJ21_2: J21.2 R165.2
NetJ21_3: J21.3 R164.2
NetNT1_1: NT1.1 U20.34(HPSNS)
NetQ9_D: Q9.D R166.1
NetQ10_D: Q10.D R167.1
NetR155_2: R155.2 U20.2(BCLKS2)
NetR156_2: R156.2 U20.4(LRCLKS2)
NetR157_2: R157.2 U20.54(SDINS2)
NetR158_2: R158.2 U20.1(SDOUTS2)

Not connected (* = marked no-connect by the designer): U20 11(NC)* 12(NC)* 13(NC)* 14(NC)* 28(NC)* 29(NC)* 40(MIC1P/DIGMICDATA)* 41(MIC1N/DIGMICCLK)* 46(NC)*

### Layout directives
differential pair: MIC_N, MIC_P, SPKL_N, SPKL_P, SPKR_N, SPKR_P

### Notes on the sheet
- AUDIO
- Enabled by default

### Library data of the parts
C34-C36 C79 C109-C111 = 1000073: CAP CER 1UF 6.3V 20% X5R 0402; Part_Type: Capacitor; Manufacturer: Murata; Manufacturer_Part_Number: GRM155R60J105ME19D; Digi_PN: 14050543; Component_Life_Cycle_State: Proven; Area: 0.95; Project: Adjustable Foundation
C112-C117 = 1001541: CAP CER 10PF 50V 5% NP0 0402; Part_Type: Capacitor; Manufacturer: Murata; Manufacturer_Part_Number: GRM1555C1H100JA01D; Note: 14050750 = Digi No. for GE WDNU; Digi_PN: 14050362; Component_Life_Cycle_State: Reviewed; Area: 0,95; Project: KITT v0.4; Tolerance: 5; Temp_Coef: C0G, NP0
C118 C119 = 1000918: CAP CER 0.1UF 50V 10% X7R 0402; Part_Type: Capacitor; Manufacturer: TDK Corporation; Manufacturer_Part_Number: C1005X7R1H104K050BB; Digi_PN: 14050715; Component_Life_Cycle_State: Reviewed; Area: 0.95; Project: DTM3.0
C120 C124 = 1001168: as C85 on sheet 11 - USB HUB
C121-C123 C125-C129 C131 = 1001167: as C83 on sheet 11 - USB HUB
C130 = 1000970: CAP CER 2.2UF 6.3V 20% X5R 0402; Part_Type: Capacitor; Manufacturer: TDK Corporation; Manufacturer_Part_Number: C1005X5R0J225M050BC; Manufacturer_Alt_1: Taiyo Yuden; Manufacturer_Alt_1_Part_Number: JMK105BJ225MV-F; Note: 14050756 = Digi No. for GE WDNU; Digi_PN: 14050493; Component_Life_Cycle_State: Reviewed; Area: 0,5; Project: ConnectCore i.MX6 module; Tolerance: 20
C133 C134 = 1000067: as C89 on sheet 11 - USB HUB
J21 = 1002596: CONN JACK STEREO 3.5MM R/A; Part_Type: Connector; Manufacturer: CUI Inc.; Digi_PN: 18000594; Component_Life_Cycle_State: Reviewed; Area: 163.02; Project: CCWMX6_SBC board
L16-L21 = 1002041: FERRITE BEAD 1.8 KOHM 0402 1LN; Manufacturer: Murata; Manufacturer_Part_Number: BLM15HD182SN1D; Digi_PN: 21000461; Component_Life_Cycle_State: Reviewed; Area: 2.2; Project: iMX6UL+PMIC
NT1 = CAD0044: NET TIE FOR I.MX6x SOM; Component_Life_Cycle_State: Created; Area: 0,039; Project: ConnectCore i.MX6x SOM
Q5 = 1000715: as Q3 on sheet 11 - USB HUB
Q6 Q9 Q10 = 1000306: as Q12 on sheet 11 - USB HUB
R154 R169 R193 = 1000537: as R12 on sheet 11 - USB HUB
R155-R158 R164 R165 = 1000076: as R76-R79 on sheet 11 - USB HUB
R159 = 1001156: RES 2.20K OHM 1/16W 1% 0402 SMD; Part_Type: Resistor; Manufacturer: Yageo; Manufacturer_Part_Number: RC0402FR-072K2L; Note: 13051099 = Digi No. for GE WDNU; Digi_PN: 13050699; Component_Life_Cycle_State: Reviewed; Area: 0,95; Project: CCWMX6_SBC board
R166 R167 = 1000467: as R161 on sheet 11 - USB HUB
R168 R194 = 1000480: as R144 on sheet 11 - USB HUB
R170 R199 = 1000208: as R146 on sheet 11 - USB HUB
U20 = 1002001: IC CODEC AUDIO FLEXSOUND 56TQFN; Manufacturer: Maxim; Manufacturer_Part_Number: MAX98089ETN+T; Component_Life_Cycle_State: Reviewed; Area: 49; Project: iMX6UL+PMIC; Digi_PN: 16052036
U21 U25 = 1001163: as U24 on sheet 11 - USB HUB

## Sheet 14 - I2C, XBee.SchDoc: I2C, XBee
size A3; PageSetup: Record=PageOptions¦CenterHorizontal=True¦CenterVertical=True¦PrintScale=0.70¦XCorrection=1.00¦YCorrection=1.00¦PrintKind=0¦BorderSize=5000000¦LeftOffset=0¦BottomOffset=0¦Orientation=2¦PaperLength=4200¦PaperWidth=2970¦Scale=100¦PaperSource=7¦PrintQuality=600¦MediaType=1¦DitherType=10¦PaperKind=A4¦PrintScaleMode=1; Author: Juan Anzola; SheetNumber: 14; SheetTotal: 17
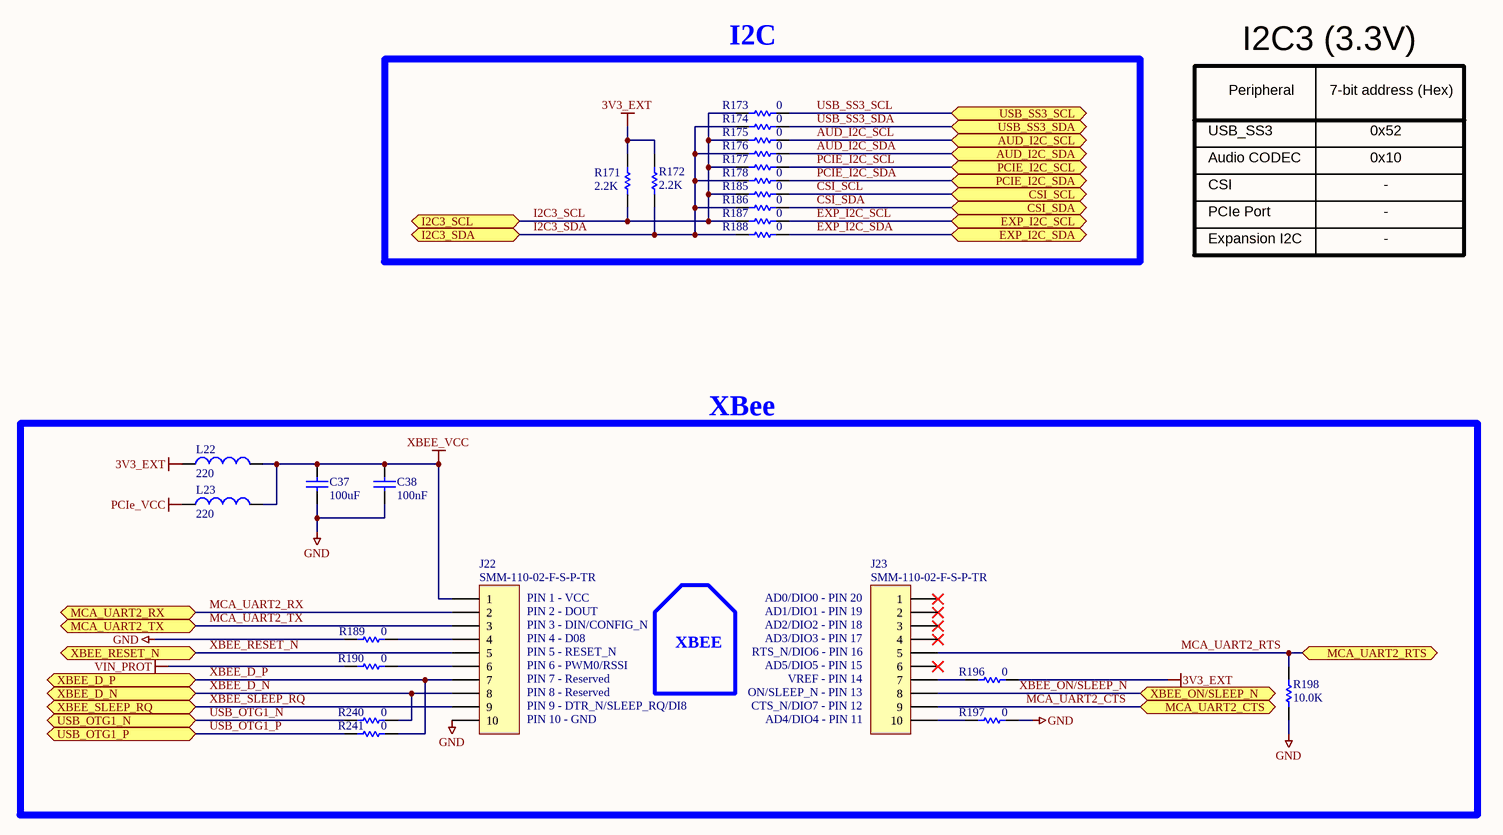
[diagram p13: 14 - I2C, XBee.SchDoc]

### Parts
C37  100uF  [CAPC3216X190N]
C38  100nF  [CAPC1005X55N]
J22  SMM-110-02-F-S-P-TR  [Samtec_SMM-110-02-F-S]
J23  SMM-110-02-F-S-P-TR  [Samtec_SMM-110-02-F-S]
L22  220  [INDC2013X110N]
L23  220  [INDC2013X110N]
R171  2.2K  [RESC1005X40N]
R172  2.2K  [RESC1005X40N]
R173  0  [RESC1005X40N]
R174  0  [RESC1005X40N]
R175  0  [RESC1005X40N]
R176  0  [RESC1005X40N]
R177  0  [RESC1005X40N]
R178  0  [RESC1005X40N]
R185  0  [RESC1005X40N]
R186  0  [RESC1005X40N]
R187  0  [RESC1005X40N]
R188  0  [RESC1005X40N]
R189  0  [RESC1005X40N]
R190  0  [RESC1005X40N]
R196  0  [RESC1005X40N]
R197  0  [RESC1005X40N]
R198  10.0K  [RESC1005X40N]
R240  0  [RESC1005X40N]
R241  0  [RESC1005X40N]

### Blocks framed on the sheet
I2C: R171-R178 R185-R188
XBee: C37 C38 J22 J23 L22 L23 R189 R190 R196-R198 R240 R241

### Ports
AUD_I2C_SCL (bidir), AUD_I2C_SDA (bidir), CSI_SCL (bidir), CSI_SDA (bidir), EXP_I2C_SCL (bidir), EXP_I2C_SDA (bidir), I2C3_SCL (bidir), I2C3_SDA (bidir), MCA_UART2_CTS (bidir), MCA_UART2_RTS (bidir), MCA_UART2_RX (bidir), MCA_UART2_TX (bidir), PCIE_I2C_SCL (bidir), PCIE_I2C_SDA (bidir), USB_OTG1_N (bidir), USB_OTG1_P (bidir), USB_SS3_SCL (bidir), USB_SS3_SDA (bidir), XBEE_D_N (bidir), XBEE_D_P (bidir), XBEE_ON/SLEEP_N (bidir), XBEE_RESET_N (bidir), XBEE_SLEEP_RQ (bidir)

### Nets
3V3_EXT: L22.1 R171.2 R172.2 R196.2
GND: C37.1 C38.1 J22.10 R189.1 R197.2 R198.1
PCIe_VCC: L23.1
VIN_PROT: R190.1
XBEE_VCC: C37.2 C38.2 J22.1 L22.2 L23.2
AUD_I2C_SCL: R175.2 ; port AUD_I2C_SCL
AUD_I2C_SDA: R176.2 ; port AUD_I2C_SDA
CSI_SCL: R185.2 ; port CSI_SCL
CSI_SDA: R186.2 ; port CSI_SDA
EXP_I2C_SCL: R187.2 ; port EXP_I2C_SCL
EXP_I2C_SDA: R188.2 ; port EXP_I2C_SDA
I2C3_SCL: R171.1 R173.1 R175.1 R177.1 R185.1 R187.1 ; port I2C3_SCL
I2C3_SDA: R172.1 R174.1 R176.1 R178.1 R186.1 R188.1 ; port I2C3_SDA
MCA_UART2_CTS: J23.9 ; port MCA_UART2_CTS
MCA_UART2_RTS: J23.5 R198.2 ; port MCA_UART2_RTS
MCA_UART2_RX: J22.2 ; port MCA_UART2_RX
MCA_UART2_TX: J22.3 ; port MCA_UART2_TX
PCIE_I2C_SCL: R177.2 ; port PCIE_I2C_SCL
PCIE_I2C_SDA: R178.2 ; port PCIE_I2C_SDA
USB_OTG1_N: R240.1 ; port USB_OTG1_N
USB_OTG1_P: R241.1 ; port USB_OTG1_P
USB_SS3_SCL: R173.2 ; port USB_SS3_SCL
USB_SS3_SDA: R174.2 ; port USB_SS3_SDA
XBEE_D_N: J22.8 R240.2 ; port XBEE_D_N
XBEE_D_P: J22.7 R241.2 ; port XBEE_D_P
XBEE_ON/SLEEP_N: J23.8 ; port XBEE_ON/SLEEP_N
XBEE_RESET_N: J22.5 ; port XBEE_RESET_N
XBEE_SLEEP_RQ: J22.9 ; port XBEE_SLEEP_RQ
NetJ22_4: J22.4 R189.2
NetJ22_6: J22.6 R190.2
NetJ23_7: J23.7 R196.1
NetJ23_10: J23.10 R197.1

Not connected (* = marked no-connect by the designer): J23 1* 2* 3* 4* 6*

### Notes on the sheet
- I2C3 (3.3V)
- USB_SS3
- Peripheral
- 7-bit address (Hex)
- 0x52
- Audio CODEC
- CSI
- 0x10
- -
- PCIe Port
- Expansion I2C
- (near J22) PIN 1 - VCC
- (near J22) PIN 2 - DOUT
- (near J23) AD0/DIO0 - PIN 20
- (near J23) AD1/DIO1 - PIN 19
- (near J22) PIN 3 - DIN/CONFIG_N
- (near J22) PIN 4 - D08
- (near J22) PIN 5 - RESET_N
- (near J22) PIN 6 - PWM0/RSSI
- XBEE
- (near J23) AD2/DIO2 - PIN 18
- (near J23) AD3/DIO3 - PIN 17
- (near J23) RTS_N/DIO6 - PIN 16
- (near J23) AD5/DIO5 - PIN 15
- (near J22) PIN 7 - Reserved
- (near J22) PIN 8 - Reserved
- (near J22) PIN 9 - DTR_N/SLEEP_RQ/DI8
- (near J22) PIN 10 - GND
- (near J23) VREF - PIN 14
- (near J23) ON/SLEEP_N - PIN 13
- (near J23) CTS_N/DIO7 - PIN 12
- (near J23) AD4/DIO4 - PIN 11

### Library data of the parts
C37 = 1000566: CAP CER 100UF 10V 20% X5R 1206; Part_Type: Capacitor; Manufacturer: TDK Corporation; Manufacturer_Part_Number: C3216X5R1A107M; Digi_PN: 14050666; Component_Life_Cycle_State: Reviewed; Area: 7.47; Project: GSM Cell PCB
C38 = 1000006: as C86 on sheet 11 - USB HUB
J22 J23 = 1001495: CONN RCPT 2MM 10POS SMD; Part_Type: Connector; Manufacturer: Samtec; Digi_PN: 19050036; Component_Life_Cycle_State: Reviewed; Area: 105; Project: CCWMX6_SBC board
L22 L23 = 1001174: as L13-L15 on sheet 11 - USB HUB
R171 R172 = 1001156: RES 2.20K OHM 1/16W 1% 0402 SMD; Part_Type: Resistor; Manufacturer: Yageo; Manufacturer_Part_Number: RC0402FR-072K2L; Digi_PN: 13050699; Component_Life_Cycle_State: Reviewed; Area: 0.95; Project: CCWMX6_SBC board; Note: 13051099 = Digi No. for GE WDNU
R173-R178 R185-R190 R196 R197 R240 R241 = 1000076: as R76-R79 on sheet 11 - USB HUB
R198 = 1000537: as R12 on sheet 11 - USB HUB

## Sheet 15 - Expansion connectors, User LEDs, RF signals.SchDoc: Expansion connectors, User LEDs, RF signals
size A3; PageSetup: Record=PageOptions¦CenterHorizontal=True¦CenterVertical=True¦PrintScale=0.70¦XCorrection=1.00¦YCorrection=1.00¦PrintKind=0¦BorderSize=5000000¦LeftOffset=0¦BottomOffset=0¦Orientation=2¦PaperLength=4200¦PaperWidth=2970¦Scale=100¦PaperSource=7¦PrintQuality=600¦MediaType=1¦DitherType=10¦PaperKind=A4¦PrintScaleMode=1; Author: Juan Anzola; SheetNumber: 15; SheetTotal: 17
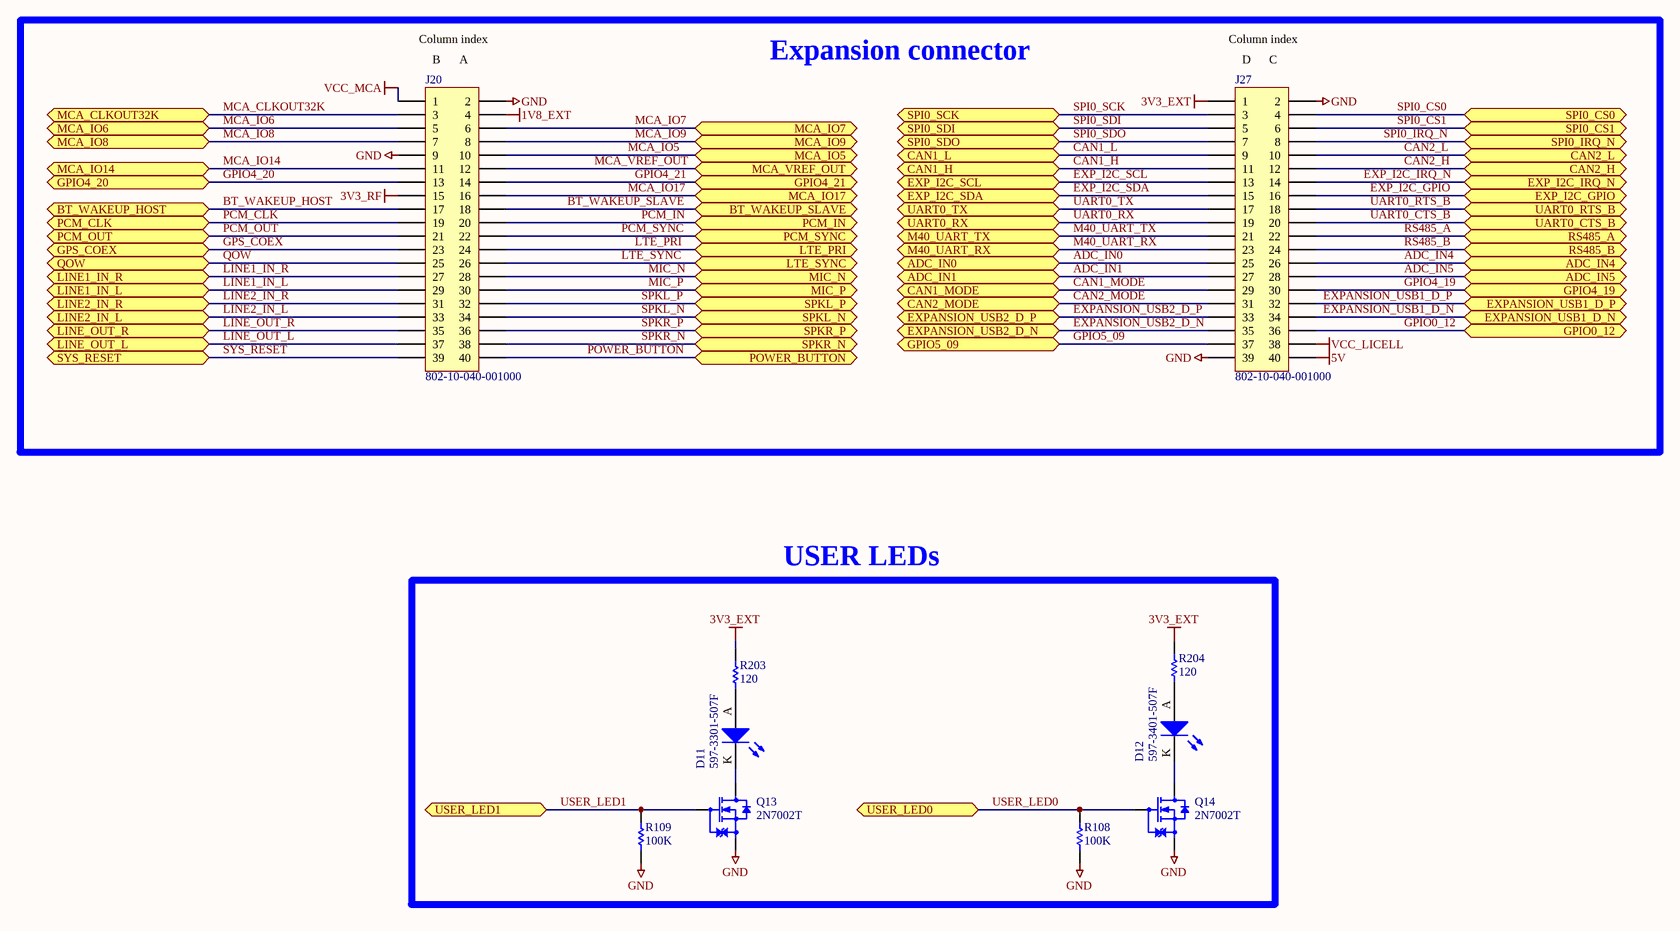
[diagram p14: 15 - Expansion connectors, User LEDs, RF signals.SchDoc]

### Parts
D11  597-3301-507F  [LEDM3020X130N]
D12  597-3401-507F  [LEDM3020X130N]
J20  802-10-040-001000  [MILLMAX_ 802-10-040-62-001000]
J27  802-10-040-001000  [MILLMAX_ 802-10-040-62-001000]
Q13  2N7002T  [SOTFL50P160X80_GSD-3N]
Q14  2N7002T  [SOTFL50P160X80_GSD-3N]
R108  100K  [RESC1005X40N]
R109  100K  [RESC1005X40N]
R203  120  [RESC1005X40N]
R204  120  [RESC1005X40N]

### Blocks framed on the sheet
Expansion connector: J20 J27
USER LEDs: D11 D12 Q13 Q14 R108 R109 R203 R204

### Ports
ADC_IN0 (bidir), ADC_IN1 (bidir), ADC_IN4 (bidir), ADC_IN5 (bidir), BT_WAKEUP_HOST (bidir), BT_WAKEUP_SLAVE (bidir), CAN1_H (bidir), CAN1_L (bidir), CAN1_MODE (bidir), CAN2_H (bidir), CAN2_L (bidir), CAN2_MODE (bidir), EXP_I2C_GPIO (bidir), EXP_I2C_IRQ_N (bidir), EXP_I2C_SCL (bidir), EXP_I2C_SDA (bidir), EXPANSION_USB1_D_N (bidir), EXPANSION_USB1_D_P (bidir), EXPANSION_USB2_D_N (bidir), EXPANSION_USB2_D_P (bidir), GPIO0_12 (bidir), GPIO4_19 (bidir), GPIO4_20 (bidir), GPIO4_21 (bidir), GPIO5_09 (bidir), GPS_COEX (bidir), LINE1_IN_L (bidir), LINE1_IN_R (bidir), LINE2_IN_L (bidir), LINE2_IN_R (bidir), LINE_OUT_L (bidir), LINE_OUT_R (bidir), LTE_PRI (bidir), LTE_SYNC (bidir), M40_UART_RX (bidir), M40_UART_TX (bidir), MCA_CLKOUT32K (bidir), MCA_IO5 (bidir), MCA_IO6 (bidir), MCA_IO7 (bidir), MCA_IO8 (bidir), MCA_IO9 (bidir), MCA_IO14 (bidir), MCA_IO17 (bidir), MCA_VREF_OUT (bidir), MIC_N (bidir), MIC_P (bidir), PCM_CLK (bidir), PCM_IN (bidir), PCM_OUT (bidir), PCM_SYNC (bidir), POWER_BUTTON (bidir), QOW (bidir), RS485_A (bidir), RS485_B (bidir), SPI0_CS0 (bidir), SPI0_CS1 (bidir), SPI0_IRQ_N (bidir), SPI0_SCK (bidir), SPI0_SDI (bidir), SPI0_SDO (bidir), SPKL_N (bidir), SPKL_P (bidir), SPKR_N (bidir), SPKR_P (bidir), SYS_RESET (bidir), UART0_CTS_B (bidir), UART0_RTS_B (bidir), UART0_RX (bidir), UART0_TX (bidir), USER_LED0 (bidir), USER_LED1 (bidir)

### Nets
1V8_EXT: J20.4
3V3_EXT: J27.1 R203.2 R204.2
3V3_RF: J20.15
5V: J27.40
GND: J20.2 J20.9 J27.2 J27.39 Q13.S Q14.S R108.2 R109.2
VCC_LICELL: J27.38
VCC_MCA: J20.1
ADC_IN0: J27.25 ; port ADC_IN0
ADC_IN1: J27.27 ; port ADC_IN1
ADC_IN4: J27.26 ; port ADC_IN4
ADC_IN5: J27.28 ; port ADC_IN5
BT_WAKEUP_HOST: J20.17 ; port BT_WAKEUP_HOST
BT_WAKEUP_SLAVE: J20.18 ; port BT_WAKEUP_SLAVE
CAN1_H: J27.11 ; port CAN1_H
CAN1_L: J27.9 ; port CAN1_L
CAN1_MODE: J27.29 ; port CAN1_MODE
CAN2_H: J27.12 ; port CAN2_H
CAN2_L: J27.10 ; port CAN2_L
CAN2_MODE: J27.31 ; port CAN2_MODE
EXP_I2C_GPIO: J27.16 ; port EXP_I2C_GPIO
EXP_I2C_IRQ_N: J27.14 ; port EXP_I2C_IRQ_N
EXP_I2C_SCL: J27.13 ; port EXP_I2C_SCL
EXP_I2C_SDA: J27.15 ; port EXP_I2C_SDA
EXPANSION_USB1_D_N: J27.34 ; port EXPANSION_USB1_D_N
EXPANSION_USB1_D_P: J27.32 ; port EXPANSION_USB1_D_P
EXPANSION_USB2_D_N: J27.35 ; port EXPANSION_USB2_D_N
EXPANSION_USB2_D_P: J27.33 ; port EXPANSION_USB2_D_P
GPIO0_12: J27.36 ; port GPIO0_12
GPIO4_19: J27.30 ; port GPIO4_19
GPIO4_20: J20.13 ; port GPIO4_20
GPIO4_21: J20.14 ; port GPIO4_21
GPIO5_09: J27.37 ; port GPIO5_09
GPS_COEX: J20.23 ; port GPS_COEX
LINE1_IN_L: J20.29 ; port LINE1_IN_L
LINE1_IN_R: J20.27 ; port LINE1_IN_R
LINE2_IN_L: J20.33 ; port LINE2_IN_L
LINE2_IN_R: J20.31 ; port LINE2_IN_R
LINE_OUT_L: J20.37 ; port LINE_OUT_L
LINE_OUT_R: J20.35 ; port LINE_OUT_R
LTE_PRI: J20.24 ; port LTE_PRI
LTE_SYNC: J20.26 ; port LTE_SYNC
M40_UART_RX: J27.23 ; port M40_UART_RX
M40_UART_TX: J27.21 ; port M40_UART_TX
MCA_CLKOUT32K: J20.3 ; port MCA_CLKOUT32K
MCA_IO5: J20.10 ; port MCA_IO5
MCA_IO6: J20.5 ; port MCA_IO6
MCA_IO7: J20.6 ; port MCA_IO7
MCA_IO8: J20.7 ; port MCA_IO8
MCA_IO9: J20.8 ; port MCA_IO9
MCA_IO14: J20.11 ; port MCA_IO14
MCA_IO17: J20.16 ; port MCA_IO17
MCA_VREF_OUT: J20.12 ; port MCA_VREF_OUT
MIC_N: J20.28 ; port MIC_N
MIC_P: J20.30 ; port MIC_P
PCM_CLK: J20.19 ; port PCM_CLK
PCM_IN: J20.20 ; port PCM_IN
PCM_OUT: J20.21 ; port PCM_OUT
PCM_SYNC: J20.22 ; port PCM_SYNC
POWER_BUTTON: J20.40 ; port POWER_BUTTON
QOW: J20.25 ; port QOW
RS485_A: J27.22 ; port RS485_A
RS485_B: J27.24 ; port RS485_B
SPI0_CS0: J27.4 ; port SPI0_CS0
SPI0_CS1: J27.6 ; port SPI0_CS1
SPI0_IRQ_N: J27.8 ; port SPI0_IRQ_N
SPI0_SCK: J27.3 ; port SPI0_SCK
SPI0_SDI: J27.5 ; port SPI0_SDI
SPI0_SDO: J27.7 ; port SPI0_SDO
SPKL_N: J20.34 ; port SPKL_N
SPKL_P: J20.32 ; port SPKL_P
SPKR_N: J20.38 ; port SPKR_N
SPKR_P: J20.36 ; port SPKR_P
SYS_RESET: J20.39 ; port SYS_RESET
UART0_CTS_B: J27.20 ; port UART0_CTS_B
UART0_RTS_B: J27.18 ; port UART0_RTS_B
UART0_RX: J27.19 ; port UART0_RX
UART0_TX: J27.17 ; port UART0_TX
USER_LED0: Q14.G R108.1 ; port USER_LED0
USER_LED1: Q13.G R109.1 ; port USER_LED1
NetD11_A: D11.A R203.1
NetD11_K: D11.K Q13.D
NetD12_A: D12.A R204.1
NetD12_K: D12.K Q14.D

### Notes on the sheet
- Column index
- (near J20) B
- (near J20) A
- (near J27) D
- (near J27) C

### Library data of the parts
D11 = 1001189: LED GREEN 573NM 1208 SMD; Manufacturer: Dialight; Note: 17050846 = Digi PN for GE WDNU II; Digi_PN: 17050183; Component_Life_Cycle_State: Reviewed; Area: 6; Project: CCWMX6_SBC board
D12 = 1001188: LED YELLOW 588NM 1208 SMD; Manufacturer: Dialight; Note: 17050842 = Digi No. for GE WDNU; Digi_PN: 17050387; Component_Life_Cycle_State: Reviewed; Area: 6; Project: CCWMX6_SBC board
J20 J27 = 1002698: CONN HEADER 40POS .100 PRESS-FIT; Part_Type: Connector; Manufacturer: Mill-Max; Manufacturer_Part_Number: 802-10-040-62-001000; Digi_PN: 18000767; Component_Life_Cycle_State: Reviewed; Area: 283,81
Q13 Q14 = 1000715: as Q3 on sheet 11 - USB HUB
R108 R109 = 1000480: as R144 on sheet 11 - USB HUB
R203 R204 = 1001158: RES 120 OHM 1/16W 1% 0402 SMD; Part_Type: Resistor; Manufacturer: Yageo; Manufacturer_Part_Number: RC0402FR-07120RL; Note: 13051102 = Digi No. for GE WDNU; Digi_PN: 13050832; Component_Life_Cycle_State: Reviewed; Area: 0,95; Project: CCWMX6_SBC board

## Sheet 16 - GPIO Table, System power rails.SchDoc: GPIO Table, System power rails
size A3; PageSetup: Record=PageOptions¦CenterHorizontal=True¦CenterVertical=True¦PrintScale=1.01¦XCorrection=1.00¦YCorrection=1.00¦PrintKind=0¦BorderSize=5000000¦LeftOffset=0¦BottomOffset=0¦Orientation=2¦PaperLength=4200¦PaperWidth=2970¦Scale=100¦PaperSource=15¦PrintQuality=600¦MediaType=1¦DitherType=10¦PrintScaleMode=1¦PaperKind=A3¦PaperIndex=8; Author: Juan Anzola; SheetNumber: 16; SheetTotal: 17
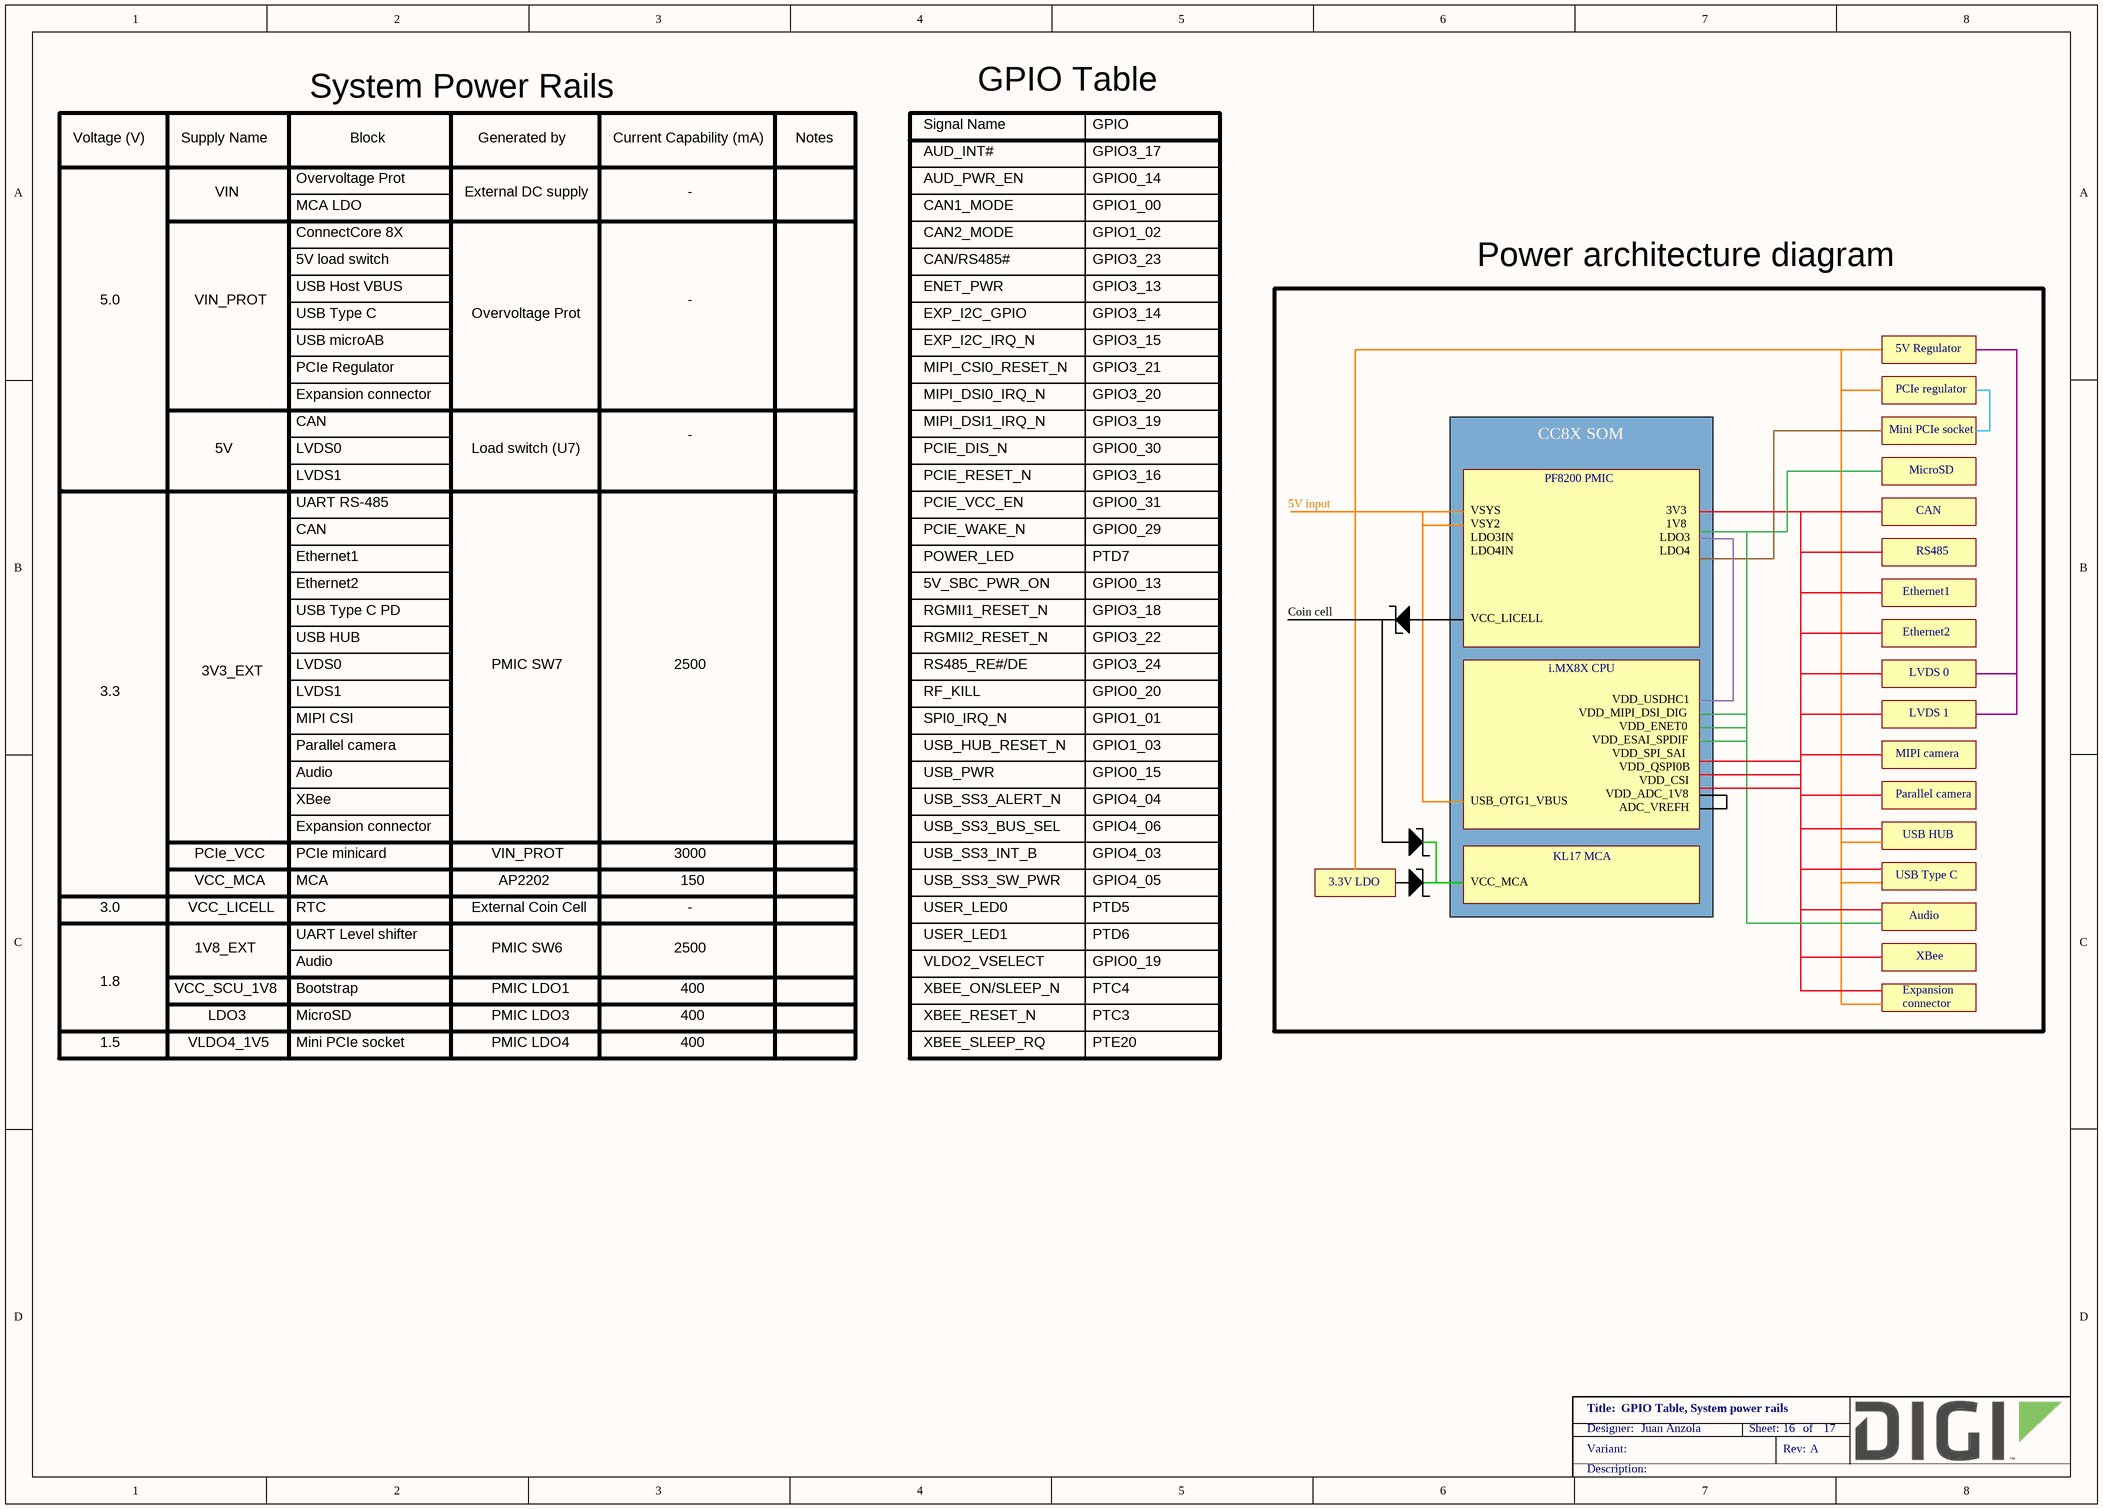
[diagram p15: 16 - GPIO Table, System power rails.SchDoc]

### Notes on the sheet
- System Power Rails
- GPIO Table
- Voltage (V)
- Supply Name
- Overvoltage Prot
- Block
- Generated by
- Current Capability (mA)
- Notes
- Signal Name
- AUD_PWR_EN
- AUD_INT#
- GPIO
- GPIO0_14
- GPIO3_17
- VIN
- MCA LDO
- ConnectCore 8X
- External DC supply
- -
- CAN2_MODE
- CAN1_MODE
- GPIO1_00
- GPIO1_02
- 5.0
- VIN_PROT
- USB Host VBUS
- USB Type C
- 5V load switch
- CAN/RS485#
- ENET_PWR
- EXP_I2C_GPIO
- GPIO3_13
- GPIO3_14
- GPIO3_23
- Power architecture diagram
- PCIe Regulator
- USB microAB
- MIPI_CSI0_RESET_N
- EXP_I2C_IRQ_N
- GPIO3_21
- GPIO3_15
- 5V Regulator
- 5V
- LVDS0
- Expansion connector
- CAN
- Load switch (U7)
- MIPI_DSI0_IRQ_N
- PCIE_DIS_N
- MIPI_DSI1_IRQ_N
- GPIO3_20
- GPIO0_30
- GPIO3_19
- CC8X SOM
- Mini PCIe socket
- PCIe regulator
- UART RS-485
- LVDS1
- PCIE_RESET_N
- PCIE_VCC_EN
- GPIO0_31
- GPIO3_16
- 5V input
- VSYS
- PF8200 PMIC
- 3V3
- MicroSD
- Ethernet1
- Ethernet2
- 5V_SBC_PWR_ON
- POWER_LED
- PCIE_WAKE_N
- GPIO0_13
- GPIO0_29
- PTD7
- VSY2
- LDO3IN
- LDO4IN
- LDO3
- LDO4
- 1V8
- RS485
- USB HUB
- USB Type C PD
- RGMII1_RESET_N
- RGMII2_RESET_N
- GPIO3_18
- GPIO3_22
- Coin cell
- VCC_LICELL
- 3.3
- 3V3_EXT
- MIPI CSI
- PMIC SW7
- 2500
- RS485_RE#/DE
- RF_KILL
- SPI0_IRQ_N
- GPIO0_20
- GPIO3_24
- GPIO1_01
- i.MX8X CPU
- VDD_MIPI_DSI_DIG
- VDD_USDHC1
- LVDS 0
- LVDS 1
- Parallel camera
- Audio
- USB_PWR
- USB_HUB_RESET_N
- GPIO0_15
- GPIO1_03
- VDD_ESAI_SPDIF
- VDD_SPI_SAI
- VDD_ENET0
- VDD_QSPI0B
- VDD_CSI
- MIPI camera
- PCIe_VCC
- XBee
- PCIe minicard
- 3000
- USB_SS3_INT_B
- USB_SS3_ALERT_N
- USB_SS3_BUS_SEL
- GPIO4_03
- GPIO4_04
- GPIO4_06
- USB_OTG1_VBUS
- VDD_ADC_1V8
- ADC_VREFH
- 3.0
- VCC_MCA
- MCA
- RTC
- External Coin Cell
- AP2202
- 150
- USER_LED0
- USB_SS3_SW_PWR
- GPIO4_05
- PTD5
- 3.3V LDO
- KL17 MCA
- 1.8
- VCC_SCU_1V8
- 1V8_EXT
- UART Level shifter
- Bootstrap
- PMIC LDO1
- PMIC SW6
- 400
- USER_LED1
- VLDO2_VSELECT
- XBEE_ON/SLEEP_N
- GPIO0_19
- PTC4
- PTD6
- Expansion
- 1.5
- VLDO4_1V5
- PMIC LDO4
- PMIC LDO3
- XBEE_SLEEP_RQ
- XBEE_RESET_N
- PTC3
- PTE20
- connector

## Sheet 17 - History, Mechanicals.SchDoc: History
size A3; PageSetup: Record=PageOptions¦CenterHorizontal=True¦CenterVertical=True¦PrintScale=1.01¦XCorrection=1.00¦YCorrection=1.00¦PrintKind=0¦BorderSize=5000000¦LeftOffset=0¦BottomOffset=0¦Orientation=2¦PaperLength=4200¦PaperWidth=2970¦Scale=100¦PaperSource=15¦PrintQuality=600¦MediaType=1¦DitherType=10¦PrintScaleMode=1¦PaperKind=A3¦PaperIndex=8; Author: Juan Anzola; SheetNumber: 17; SheetTotal: 17
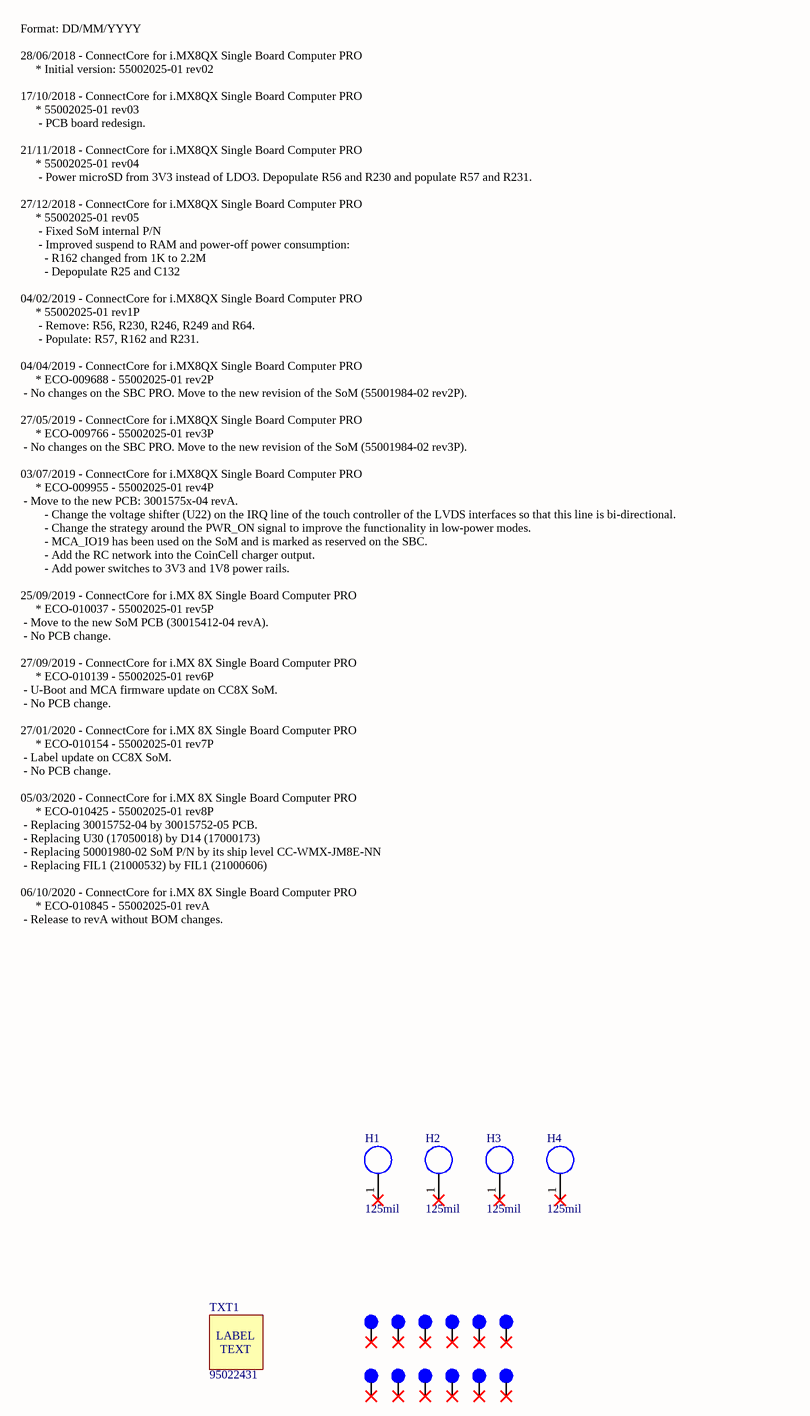
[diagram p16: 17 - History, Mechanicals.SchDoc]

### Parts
FIDUCIAL1  40mil FID  [fiducial_40mil_round]  (value not drawn)  (no BOM)
FIDUCIAL2  40mil FID  [fiducial_40mil_round]  (value not drawn)  (no BOM)
FIDUCIAL3  40mil FID  [fiducial_40mil_round]  (value not drawn)  (no BOM)
FIDUCIAL4  40mil FID  [fiducial_40mil_round]  (value not drawn)  (no BOM)
FIDUCIAL5  40mil FID  [fiducial_40mil_round]  (value not drawn)  (no BOM)
FIDUCIAL6  40mil FID  [fiducial_40mil_round]  (value not drawn)  (no BOM)
FIDUCIAL7  40mil FID  [fiducial_40mil_round]  (value not drawn)  (no BOM)
FIDUCIAL8  40mil FID  [fiducial_40mil_round]  (value not drawn)  (no BOM)
FIDUCIAL9  40mil FID  [fiducial_40mil_round]  (value not drawn)  (no BOM)
FIDUCIAL10  40mil FID  [fiducial_40mil_round]  (value not drawn)  (no BOM)
FIDUCIAL11  40mil FID  [fiducial_40mil_round]  (value not drawn)  (no BOM)
FIDUCIAL12  40mil FID  [fiducial_40mil_round]  (value not drawn)  (no BOM)
H1  125mil  [MH_185_125_NP]  (no BOM)
H2  125mil  [MH_185_125_NP]  (no BOM)
H3  125mil  [MH_185_125_NP]  (no BOM)
H4  125mil  [MH_185_125_NP]  (no BOM)
TXT1  95022431  (mechanical)

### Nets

Not connected (* = marked no-connect by the designer): FIDUCIAL1 1(Fid_1)*; FIDUCIAL2 1(Fid_1)*; FIDUCIAL3 1(Fid_1)*; FIDUCIAL4 1(Fid_1)*; FIDUCIAL5 1(Fid_1)*; FIDUCIAL6 1(Fid_1)*; FIDUCIAL7 1(Fid_1)*; FIDUCIAL8 1(Fid_1)*; FIDUCIAL9 1(Fid_1)*; FIDUCIAL10 1(Fid_1)*; FIDUCIAL11 1(Fid_1)*; FIDUCIAL12 1(Fid_1)*; H1 1(TOOL)*; H2 1(TOOL)*; H3 1(TOOL)*; H4 1(TOOL)*

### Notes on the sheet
- Format: DD/MM/YYYY
  28/06/2018 - ConnectCore for i.MX8QX Single Board Computer PRO
  * Initial version: 55002025-01 rev02
  17/10/2018 - ConnectCore for i.MX8QX Single Board Computer PRO
  * 55002025-01 rev03
  - PCB board redesign.
  21/11/2018 - ConnectCore for i.MX8QX Single Board Computer PRO
  * 55002025-01 rev04
  - Power microSD from 3V3 instead of LDO3. Depopulate R56 and R230 and populate R57 and R231.
  27/12/2018 - ConnectCore for i.MX8QX Single Board Computer PRO
  * 55002025-01 rev05
  - Fixed SoM internal P/N
  - Improved suspend to RAM and power-off power consumption:
  - R162 changed from 1K to 2.2M
  - Depopulate R25 and C132
  04/02/2019 - ConnectCore for i.MX8QX Single Board Computer PRO
  * 55002025-01 rev1P
  - Remove: R56, R230, R246, R249 and R64.
  - Populate: R57, R162 and R231.
  04/04/2019 - ConnectCore for i.MX8QX Single Board Computer PRO
  * ECO-009688 - 55002025-01 rev2P
  - No changes on the SBC PRO. Move to the new revision of the SoM (55001984-02 rev2P).
  27/05/2019 - ConnectCore for i.MX8QX Single Board Computer PRO
  * ECO-009766 - 55002025-01 rev3P
  - No changes on the SBC PRO. Move to the new revision of the SoM (55001984-02 rev3P).
  03/07/2019 - ConnectCore for i.MX8QX Single Board Computer PRO
  * ECO-009955 - 55002025-01 rev4P
  - Move to the new PCB: 3001575x-04 revA.
  - Change the voltage shifter (U22) on the IRQ line of the touch controller of the LVDS interfaces so that this line is bi-directional.
  - Change the strategy around the PWR_ON signal to improve the functionality in low-power modes.
  - MCA_IO19 has been used on the SoM and is marked as reserved on the SBC.
  - Add the RC network into the CoinCell charger output.
  - Add power switches to 3V3 and 1V8 power rails.
  25/09/2019 - ConnectCore for i.MX 8X Single Board Computer PRO
  * ECO-010037 - 55002025-01 rev5P
  - Move to the new SoM PCB (30015412-04 revA).
  - No PCB change.
  27/09/2019 - ConnectCore for i.MX 8X Single Board Computer PRO
  * ECO-010139 - 55002025-01 rev6P
  - U-Boot and MCA firmware update on CC8X SoM.
  - No PCB change.
  27/01/2020 - ConnectCore for i.MX 8X Single Board Computer PRO
  * ECO-010154 - 55002025-01 rev7P
  - Label update on CC8X SoM.
  - No PCB change.
  05/03/2020 - ConnectCore for i.MX 8X Single Board Computer PRO
  * ECO-010425 - 55002025-01 rev8P
  - Replacing 30015752-04 by 30015752-05 PCB.
  - Replacing U30 (17050018) by D14 (17000173)
  - Replacing 50001980-02 SoM P/N by its ship level CC-WMX-JM8E-NN
  - Replacing FIL1 (21000532) by FIL1 (21000606)
  06/10/2020 - ConnectCore for i.MX 8X Single Board Computer PRO
  * ECO-010845 - 55002025-01 revA
  - Release to revA without BOM changes.

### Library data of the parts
FIDUCIAL1-FIDUCIAL12 = CAD0023: 40 Mil Round Fiducial; Part_Type: Mechanical; Component_Life_Cycle_State: Reviewed; Area: 1; Project: SDR Prototype RF Board
H1-H4 = CAD0006: NPTH for Tooling, 0.125in dia.; Part_Type: Mechanical; Component_Life_Cycle_State: Proven; Area: 0.98; Project: Adjustable Foundation
TXT1 = CAD0092: 95022431, LABEL TEXT FOR CC8X SOM 55002025-01; Noplace: False; Component_Life_Cycle_State: Pending; Area: 0; Project: DIGI CC8X SOM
